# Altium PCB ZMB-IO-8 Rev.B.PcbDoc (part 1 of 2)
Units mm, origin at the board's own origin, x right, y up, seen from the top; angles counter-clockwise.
Board outline 164 x 122 mm, 8 copper layers (Top Layer, L2, L3, L4, L5, L6, L7, Bottom Layer), stack 1.966 mm thick; 31 components, 171 nets, 626 pads, 99 vias.
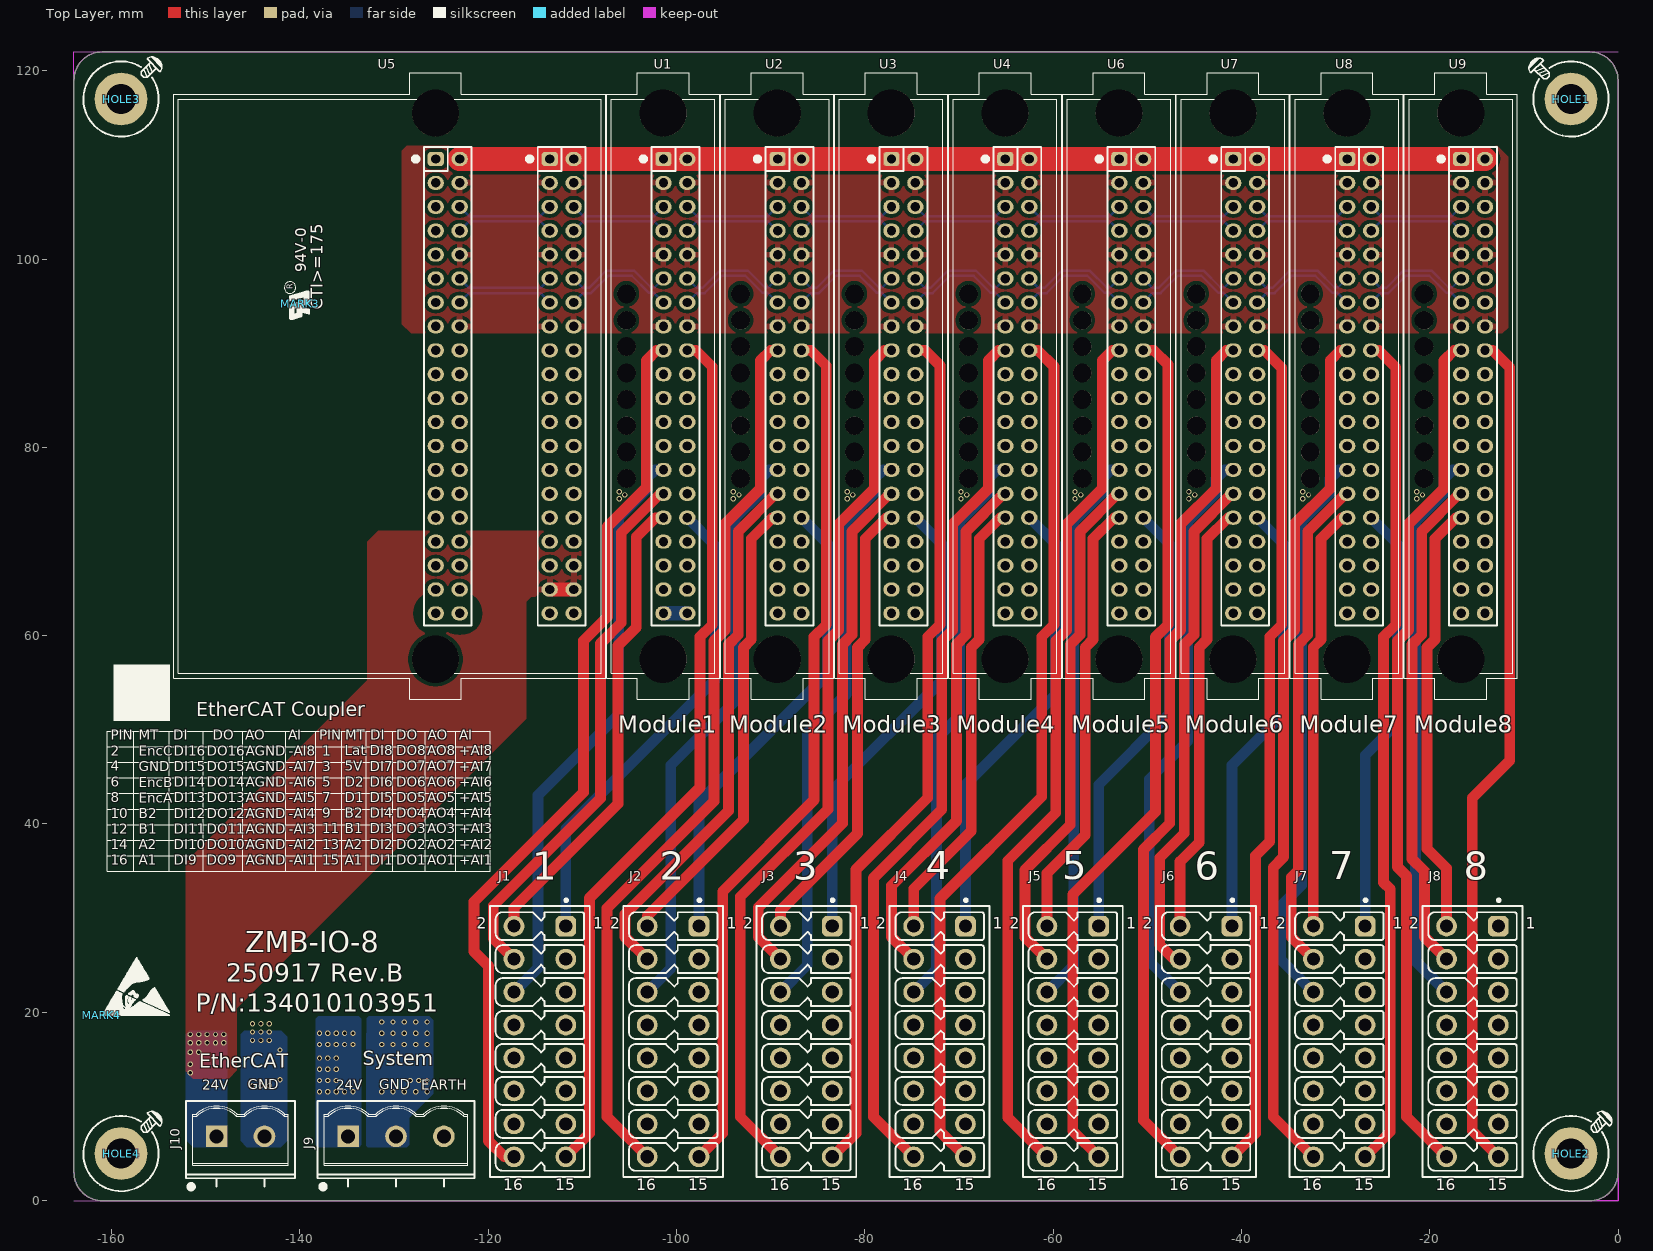
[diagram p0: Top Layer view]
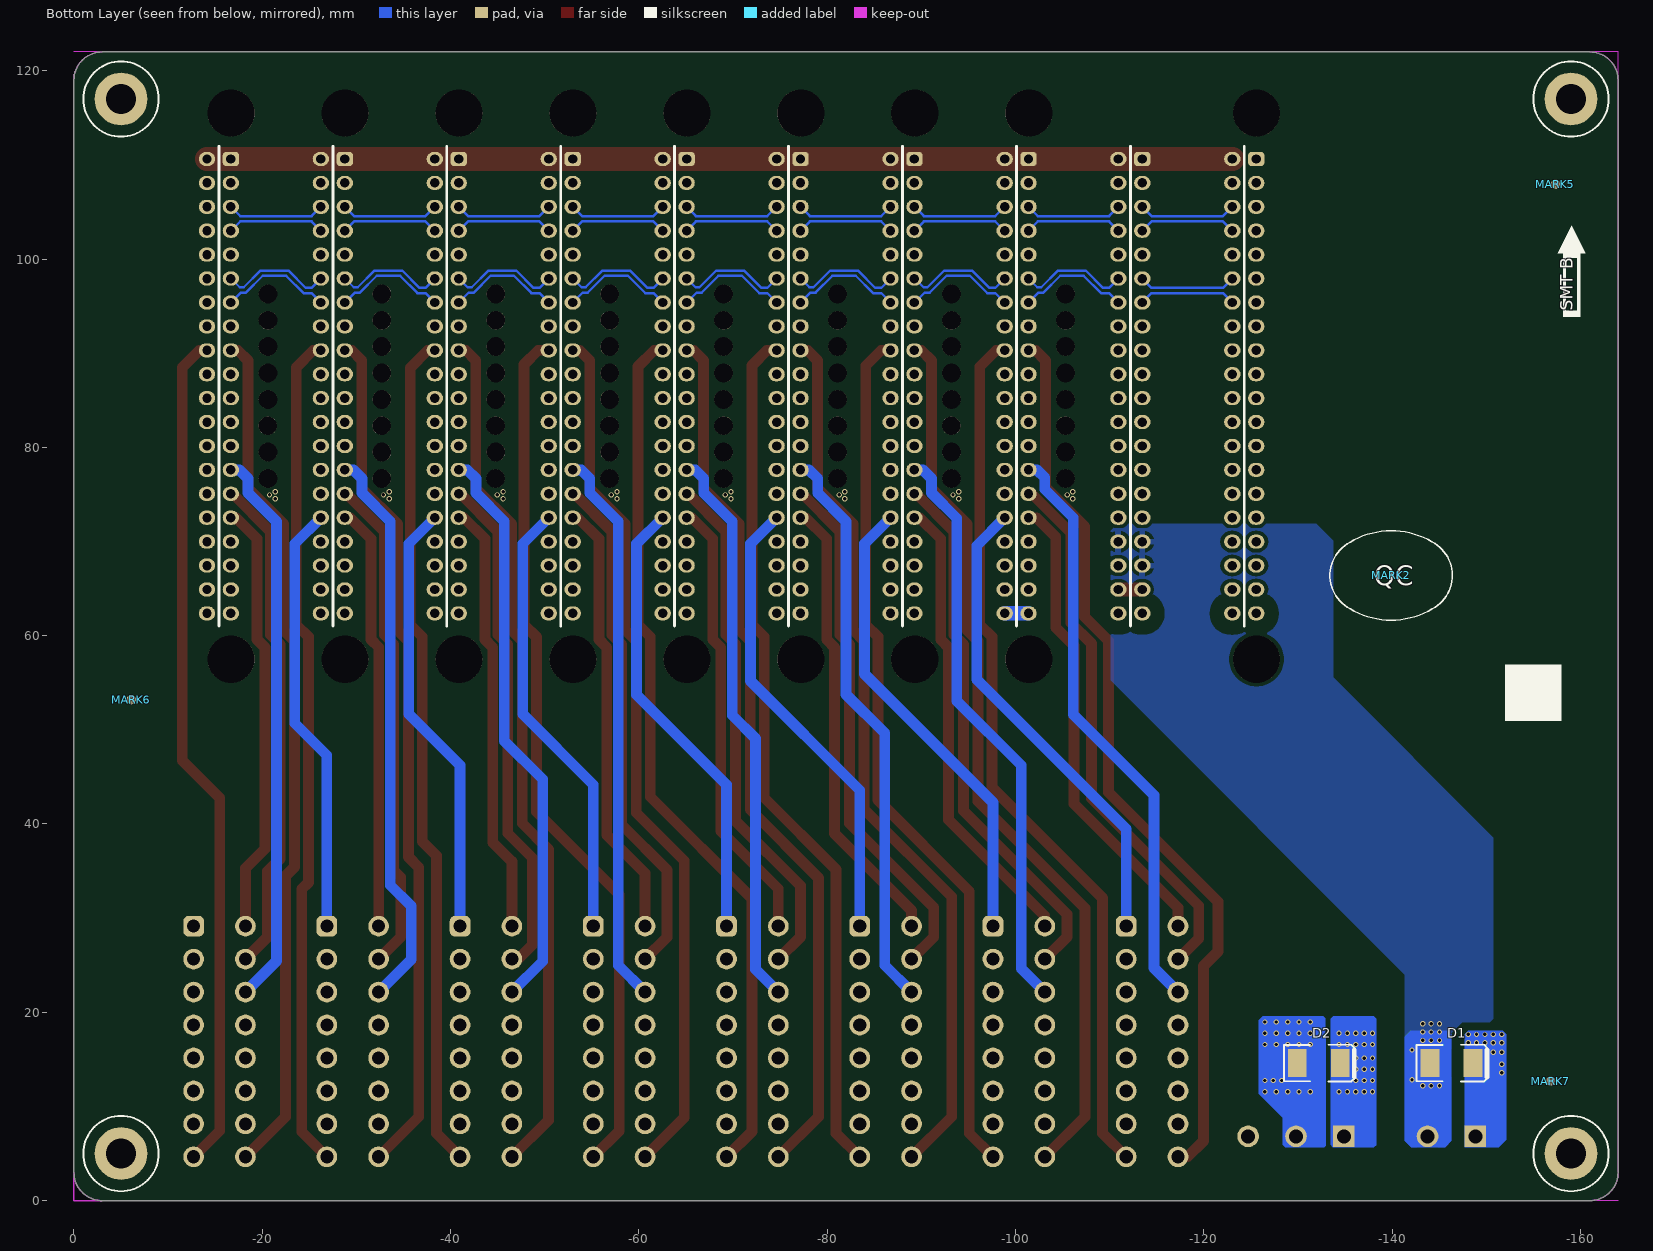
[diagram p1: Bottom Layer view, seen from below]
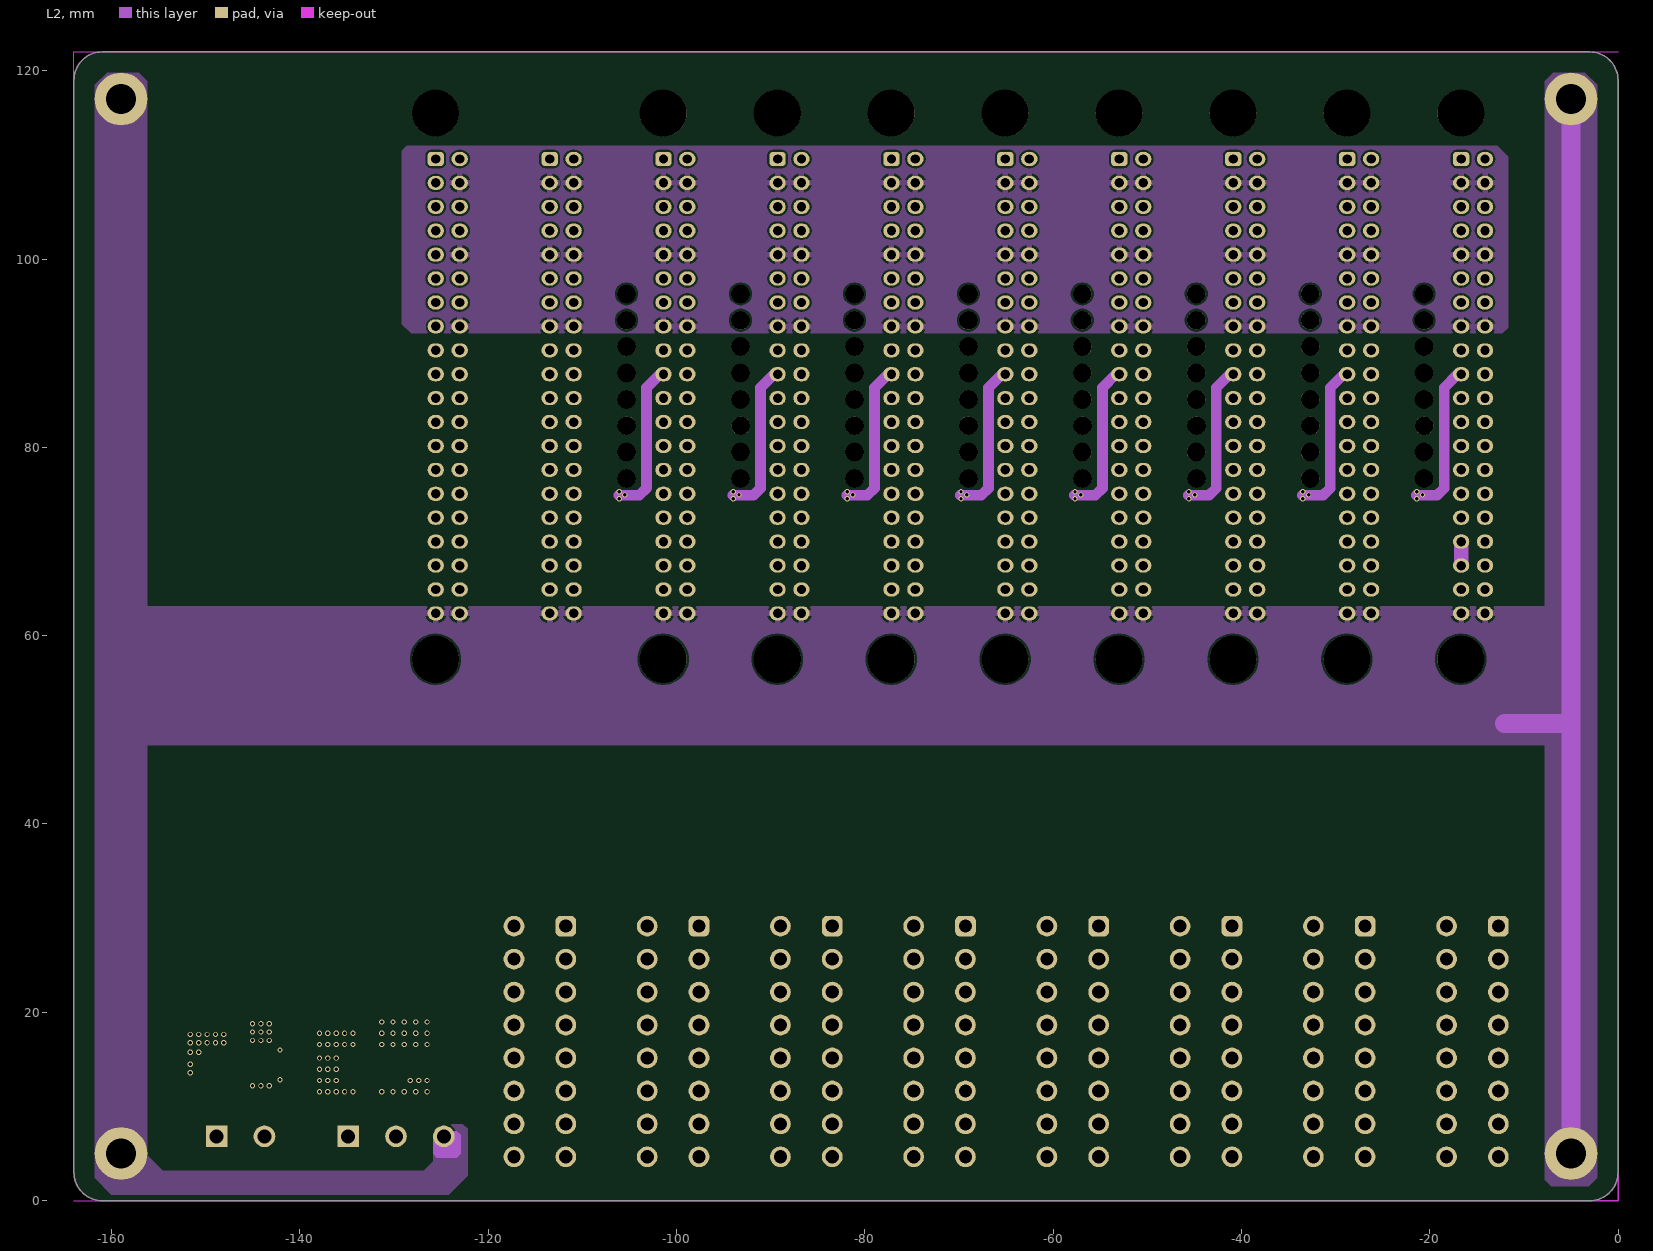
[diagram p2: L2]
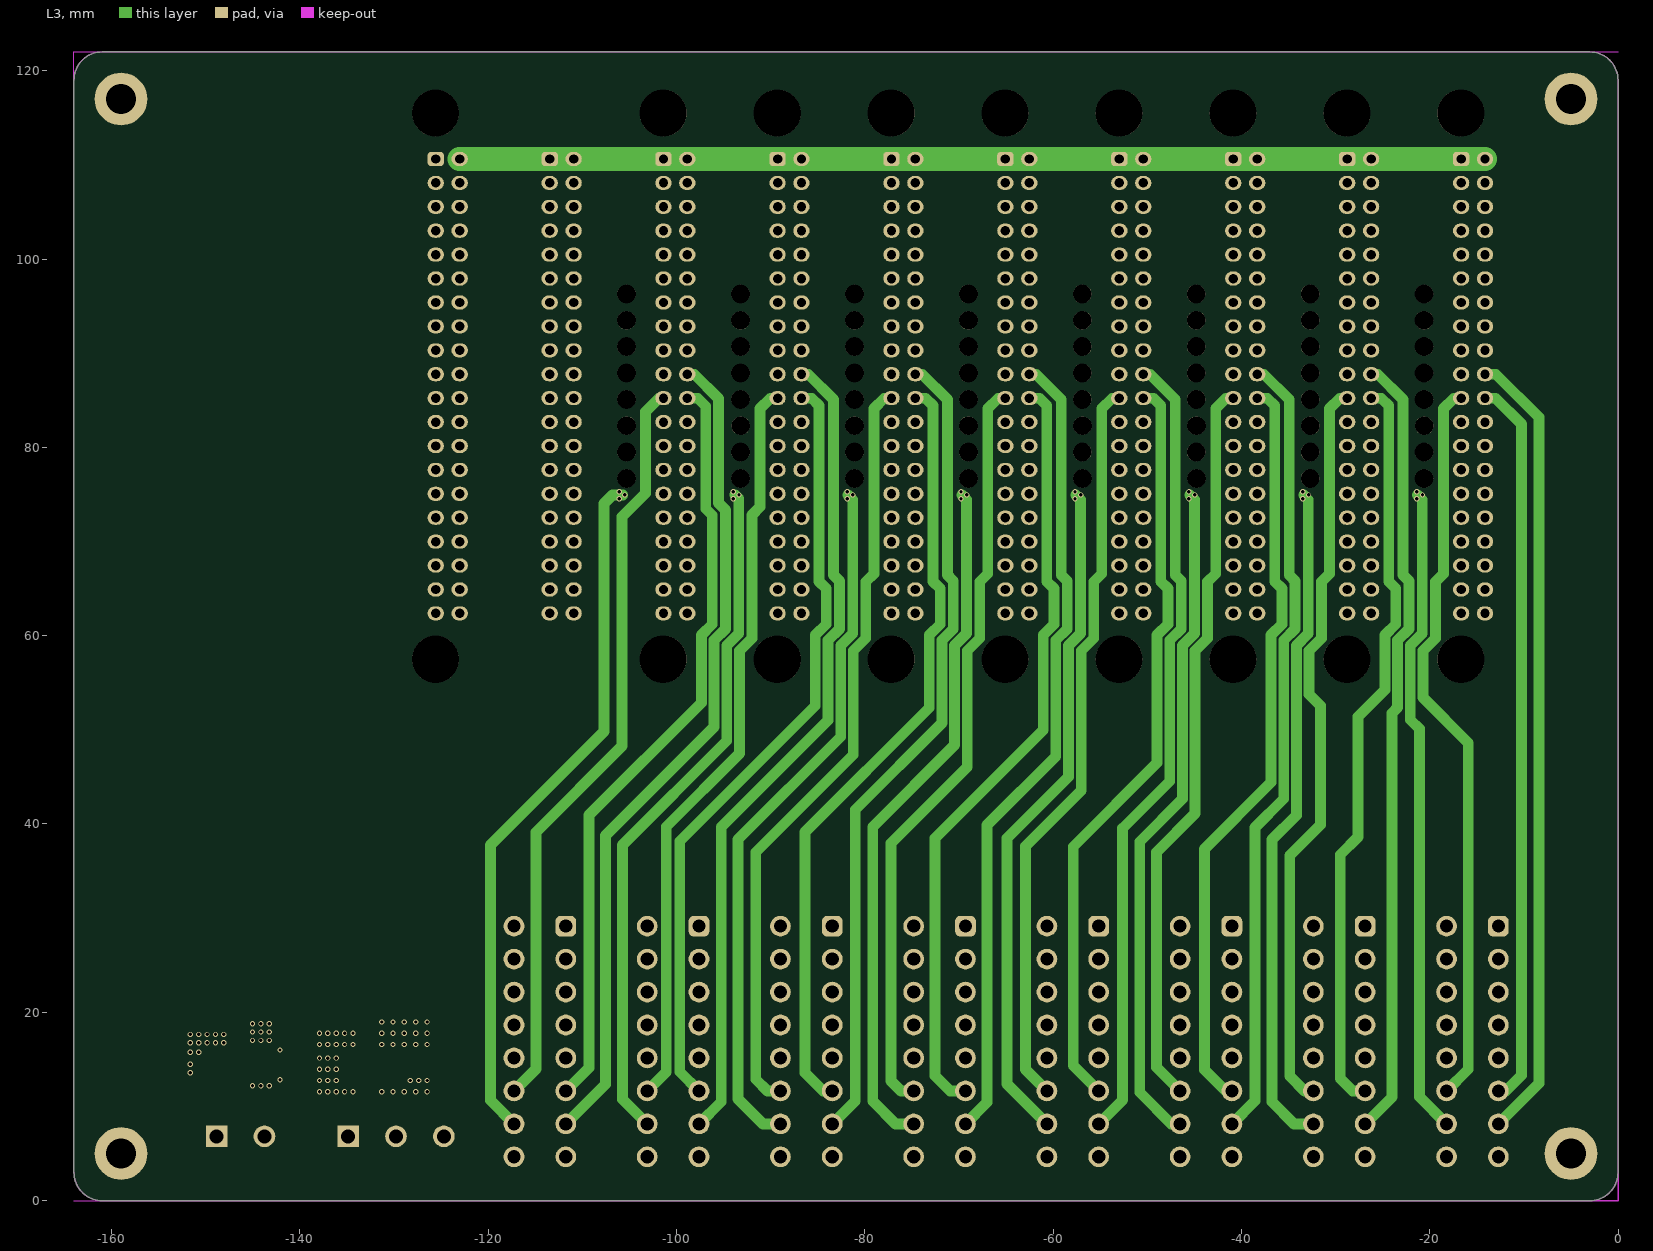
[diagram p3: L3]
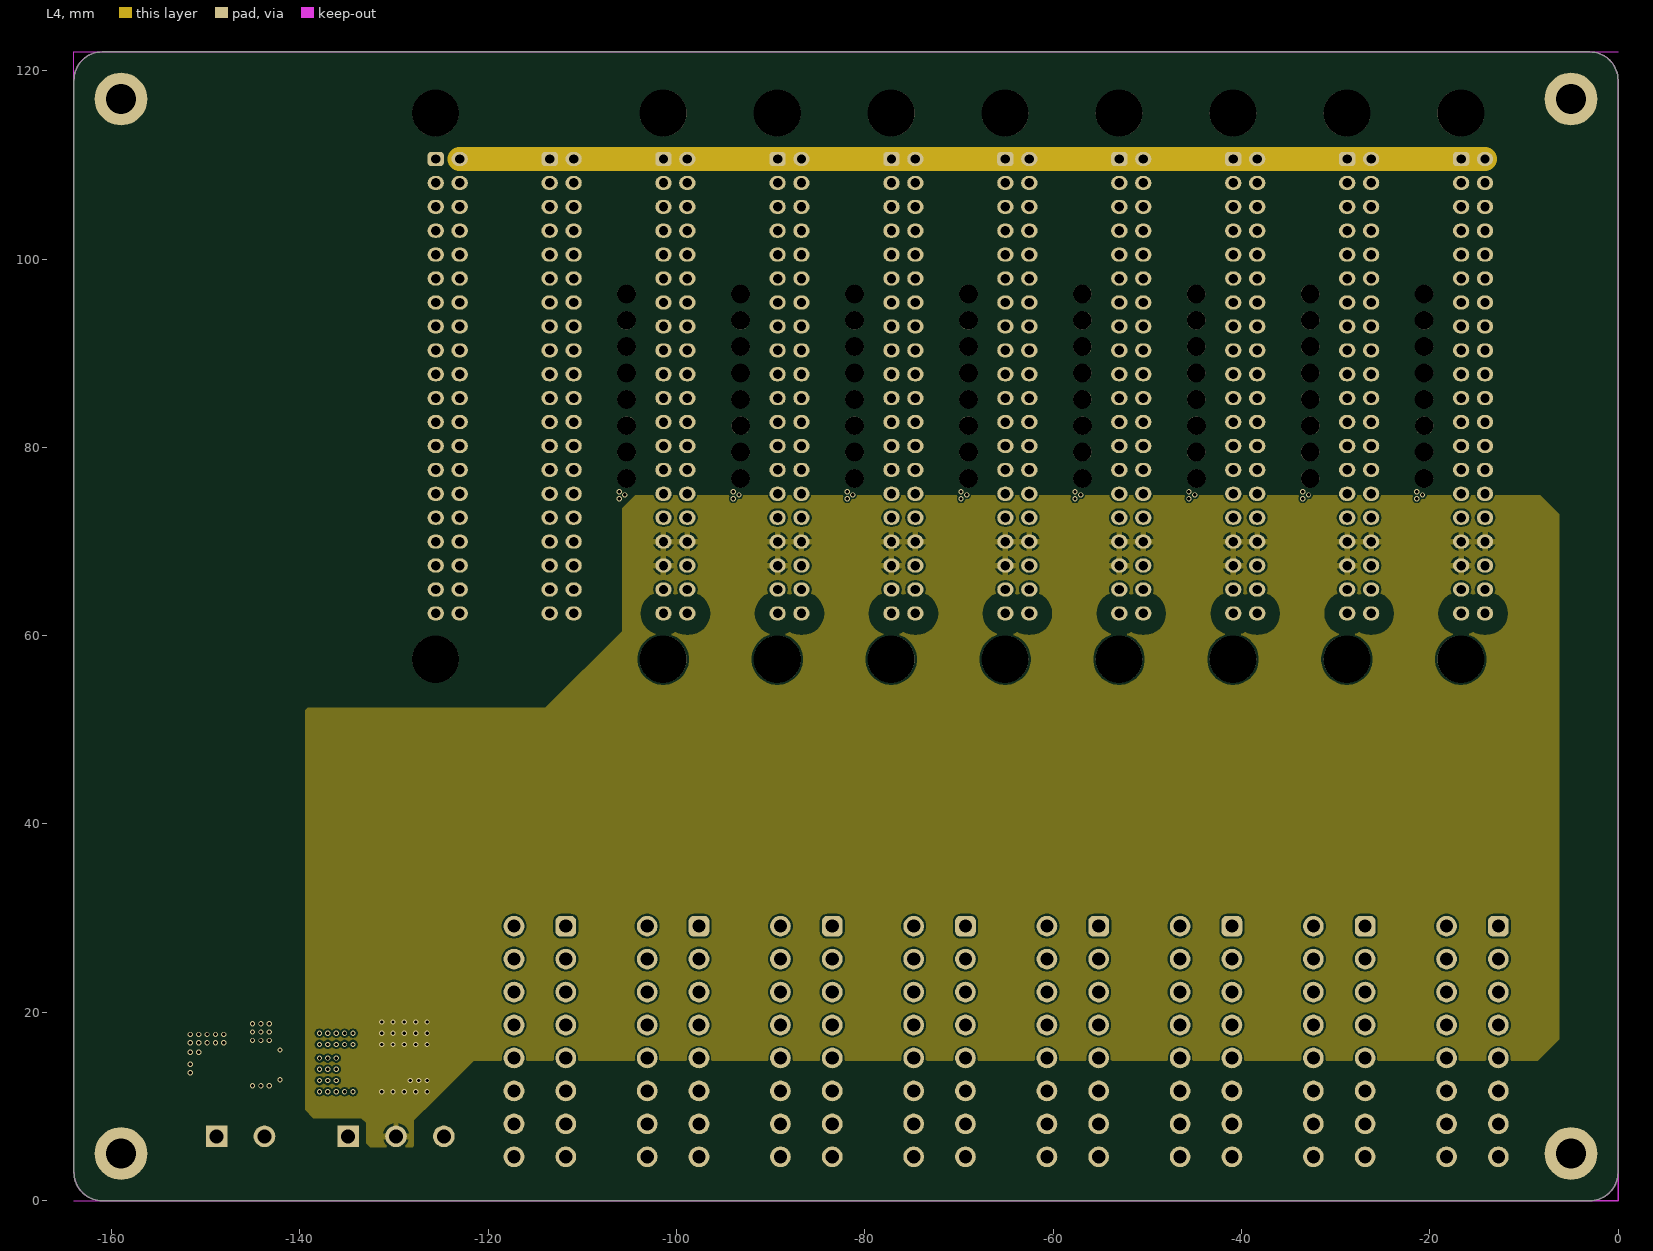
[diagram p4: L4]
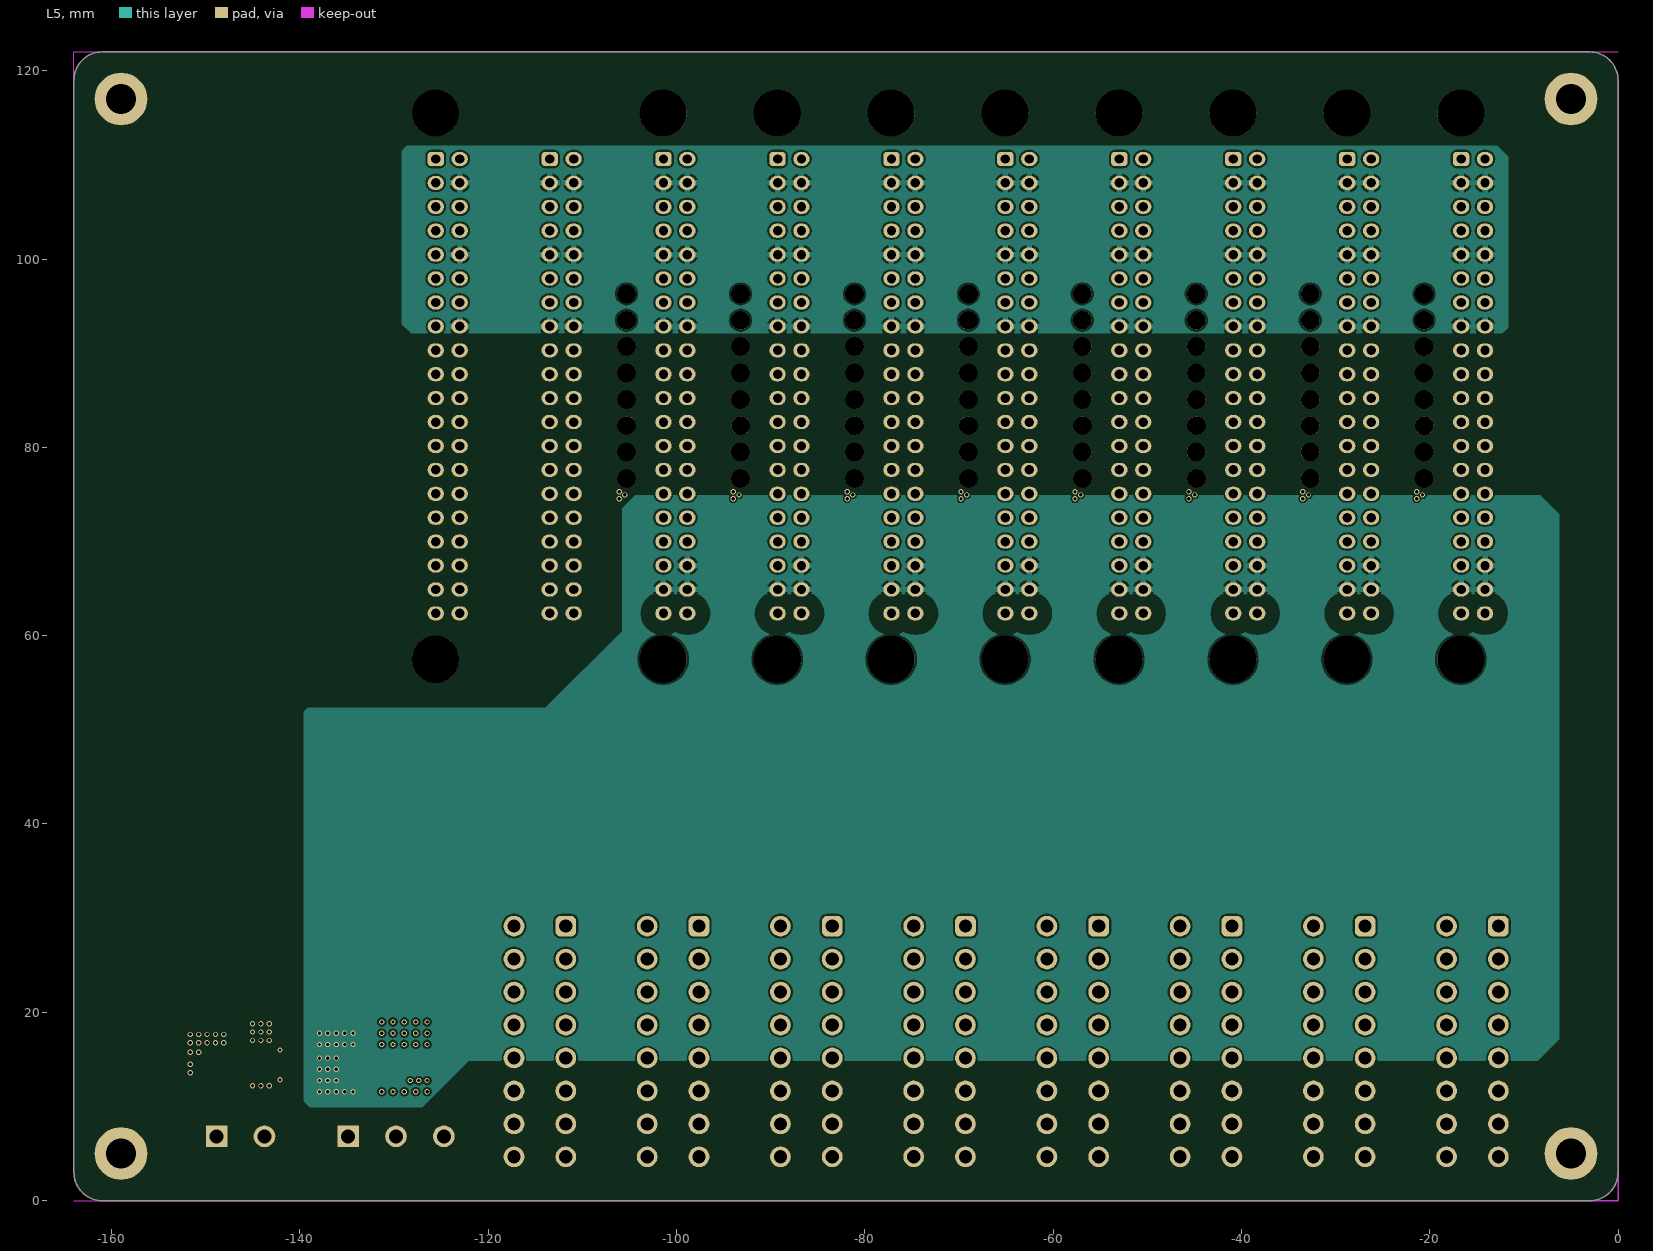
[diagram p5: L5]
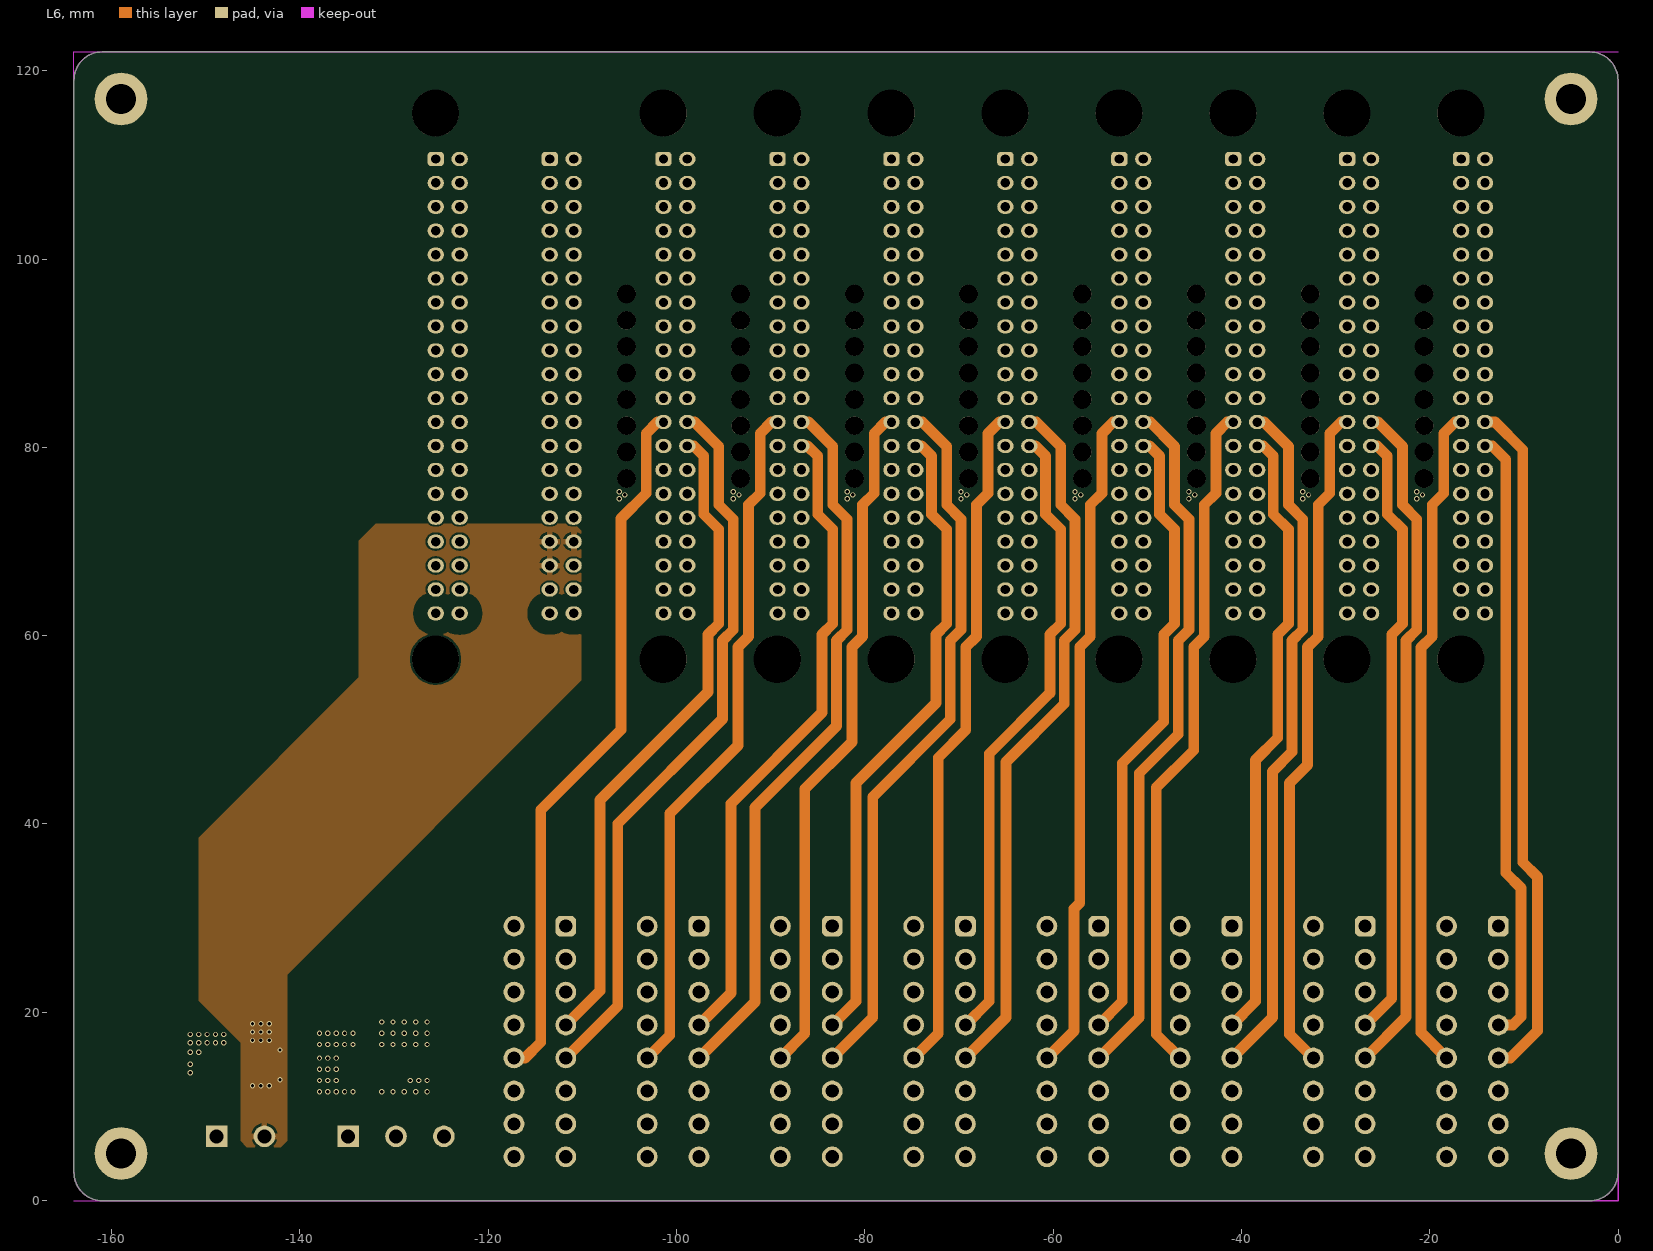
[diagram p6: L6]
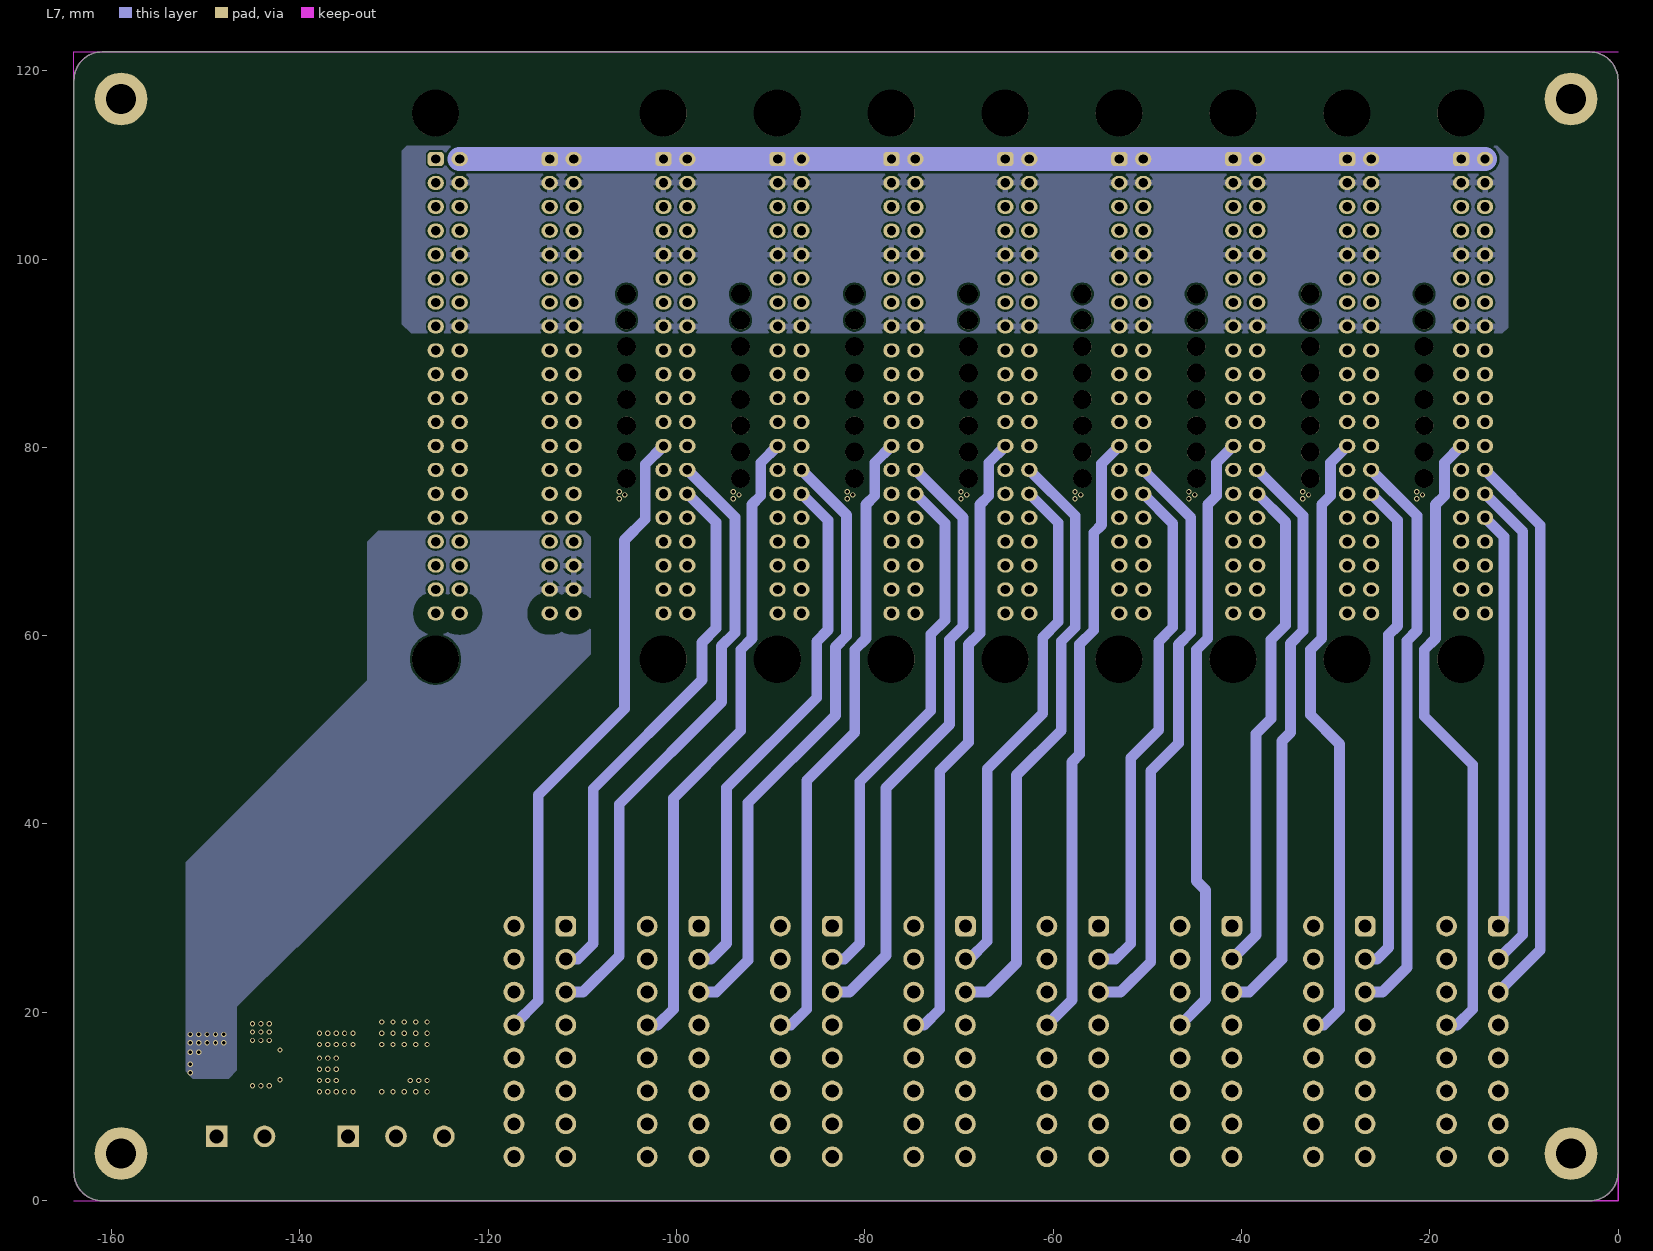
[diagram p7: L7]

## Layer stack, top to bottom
Top Solder: solder mask 0.0102, Solder Resist, Dk 3.2
Top Layer: signal copper 0.07
Dielectric 1: prepreg 0.081, FR-4, Dk 3.8
L2: signal copper 0.07
Dielectric 4: prepreg 0.0711, PP-006, Dk 4.1
L3: signal copper 0.035
Dielectric 6: prepreg 0.0711, PP-006, Dk 4.1
L4: signal copper 0.035
Dielectric 2: core 1.1, FR-4, Dk 4.2
L5: signal copper 0.035
Dielectric 7: prepreg 0.0711, PP-006, Dk 4.1
L6: signal copper 0.035
Dielectric 5: prepreg 0.0711, PP-006, Dk 4.1
L7: signal copper 0.07
Dielectric 3: prepreg 0.081, FR-4, Dk 3.8
Bottom Layer: signal copper 0.07
Bottom Solder: solder mask 0.0102, Solder Resist, Dk 3.2

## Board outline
-161,0 cw(c-161,3) -164,3 -164,119 cw(c-161,119) -161,122 -3,122 cw(c-3,119) 0,119 0,3 cw(c-3,3) -3,0

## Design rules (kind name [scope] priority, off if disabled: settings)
Clearance Clearance_diff2poly [InAnyDifferentialPair and IsTrack vs InPoly] p1: gap=0.508 ignorepadtopadclearanceinfootprint=FALSE except(0: Arc-Hole Track-Hole SMDPad-Hole THPad-Hole Via-Hole Fill-Hole Poly-Hole Region-Hole Text-Hole)
Clearance Clearance_moto2other [InNetClass('moto') vs InAnyNet > InNetClass('moto')] p2: gap=1.016 ignorepadtopadclearanceinfootprint=FALSE except(0: Arc-Hole Track-Hole SMDPad-Hole THPad-Hole Via-Hole Fill-Hole Poly-Hole Region-Hole Text-Hole)
Clearance Clearance_CAP90/270H->5 [((HasFootprint('0201C') or HasFootprint('0402C*') or HasFootprint('0603C*') or HasFootprint('0805C*') or HasFootprint('1210C') or HasFootprint('2220C')) and ((Rotation='0') or (Rotation='180'))) or (HasFootprint('1206C*')) and ((Rotation='90') or (Rotation='270')) vs (IsTrack > InAnyComponent) and OnLayer('Keep-Out Layer')  and (Y1=Y2)] p3: gap=5 ignorepadtopadclearanceinfootprint=FALSE except(0: Arc-Hole Track-Hole SMDPad-Hole THPad-Hole Via-Hole Fill-Hole Poly-Hole Region-Hole Text-Hole) // ZLG
Clearance Clearance_CAP0/180H->2 [((HasFootprint('0201C') or HasFootprint('0402C*') or HasFootprint('0603C*') or HasFootprint('0805C*') or HasFootprint('1210C') or HasFootprint('2220C')) and ((Rotation='90') or (Rotation='270'))) or (HasFootprint('1206C*')) and ((Rotation='0') or (Rotation='180')) vs (IsTrack > InAnyComponent) and OnLayer('Keep-Out Layer')  and (Y1=Y2)] p4: gap=2 ignorepadtopadclearanceinfootprint=FALSE except(0: Arc-Hole Track-Hole SMDPad-Hole THPad-Hole Via-Hole Fill-Hole Poly-Hole Region-Hole Text-Hole) // ZLG
Clearance Clearance_CAP90/270V>2 [((HasFootprint('0201C') or HasFootprint('0402C*') or HasFootprint('0603C*') or HasFootprint('0805C*') or HasFootprint('1210C') or HasFootprint('2220C')) and ((Rotation='0') or (Rotation='180'))) or (HasFootprint('1206C*')) and ((Rotation='90') or (Rotation='270')) vs (IsTrack > InAnyComponent) and OnLayer('Keep-Out Layer')  and (X1=X2)] p5: gap=2 ignorepadtopadclearanceinfootprint=FALSE except(0: Arc-Hole Track-Hole SMDPad-Hole THPad-Hole Via-Hole Fill-Hole Poly-Hole Region-Hole Text-Hole) // ZLG
Clearance Clearance_CAP0/180V>5 [((HasFootprint('0201C') or HasFootprint('0402C*') or HasFootprint('0603C*') or HasFootprint('0805C*') or HasFootprint('1210C') or HasFootprint('2220C')) and ((Rotation='90') or (Rotation='270'))) or (HasFootprint('1206C*')) and ((Rotation='0') or (Rotation='180')) vs (IsTrack > InAnyComponent) and OnLayer('Keep-Out Layer')  and (X1=X2)] p6: gap=5 ignorepadtopadclearanceinfootprint=FALSE except(0: Arc-Hole Track-Hole SMDPad-Hole THPad-Hole Via-Hole Fill-Hole Poly-Hole Region-Hole Text-Hole) // ZLG
Clearance Clearance_Keepout [OnLayer('Keep-Out Layer')] p7: gap=0.508 ignorepadtopadclearanceinfootprint=FALSE except(0: Arc-Hole Track-Hole SMDPad-Hole THPad-Hole Via-Hole Fill-Hole Poly-Hole Region-Hole Text-Hole) // ZLG
Clearance Clearance_Wave_Height<0.6mm [OnLayer('Bottom Layer') and IsSMTPin and (HasFootprint('0201*') or HasFootprint('0402*') or HasFootprint('0603R*')) > HasFootprint('0402C-H0.8') vs IsPadHoleValid > (IsFree or  HasFootprint('HOLE-*') or HasFootprint('SMDSTUD-*') or  HasFootprint('Mou-Hole-*') or HasFootprint('SMT*') or HasFootprint('HRS_*') or HasFootprint('MEDC52-32F-PCIE-*') or HasFootprint('PHONE-JACK*') or HasFootprint('SD-CARD-Panasonic')  or HasFootprint('SIM-ST-SIM-006P-NB2') or HasFootprint('MICROUSB-ST-USB-002B-1') or HasFootprint('USB_ST-USB-3316-2') )] p8: gap=3 ignorepadtopadclearanceinfootprint=FALSE except(0: Arc-Hole Track-Hole SMDPad-Hole THPad-Hole Via-Hole Fill-Hole Poly-Hole Region-Hole Text-Hole) // ZLG
Clearance Clearance_Wave_All [OnLayer('Bottom Layer') and IsSMTPin vs IsPadHoleValid > (IsFree or  HasFootprint('HOLE-*') or HasFootprint('SMDSTUD-*') or  HasFootprint('Mou-Hole-*') or HasFootprint('SMT*') or HasFootprint('HRS_*') or HasFootprint('MEDC52-32F-PCIE-*') or HasFootprint('PHONE-JACK*') or HasFootprint('SD-CARD-Panasonic')  or HasFootprint('SIM-ST-SIM-006P-NB2') or HasFootprint('MICROUSB-ST-USB-002B-1') or HasFootprint('USB_ST-USB-3316-2') )] p9: gap=4 ignorepadtopadclearanceinfootprint=FALSE except(0: Arc-Hole Track-Hole SMDPad-Hole THPad-Hole Via-Hole Fill-Hole Poly-Hole Region-Hole Text-Hole) // ZLG
Clearance Clearance_earth2other [InNet('EARTH*') or InNet('PGND*') vs InPoly] p10: gap=1.524 ignorepadtopadclearanceinfootprint=FALSE except(0: Arc-Hole Track-Hole SMDPad-Hole THPad-Hole Via-Hole Fill-Hole Poly-Hole Region-Hole Text-Hole) // ZLG
Clearance Clearance_TP [HasFootprint('PAD-40') vs HasFootprint('PAD-40')] p11: gap=1.27 ignorepadtopadclearanceinfootprint=FALSE except(0: Arc-Hole Track-Hole SMDPad-Hole THPad-Hole Via-Hole Fill-Hole Poly-Hole Region-Hole Text-Hole) // ZLG
Clearance Clearance_Hole2Pad [IsVia vs IsPad  > ( HasFootprint('QF*-*N*') or HasFootprint('SO*-*N*') or HasFootprint('PQFN*') or HasFootprint('PSON*') or HasFootprint('DFN*') or HasFootprint('DPAK*') or HasFootprint('PVQF*') )] p12: gap=0 ignorepadtopadclearanceinfootprint=FALSE // ZLG
Clearance Clearance_Surface [OnLayer('Top Layer') or OnLayer('Bottom Layer')] p13: gap=0.203 ignorepadtopadclearanceinfootprint=FALSE except(0: Arc-Hole Track-Hole SMDPad-Hole THPad-Hole Via-Hole Fill-Hole Poly-Hole Region-Hole Text-Hole; 0.254: Via-Poly; 0.305: Poly-Region Poly-Text; 0.381: Arc-Poly Track-Poly SMDPad-Poly THPad-Poly Fill-Poly Poly-Poly) // ZLG
Clearance [All] p14: gap=0.203 ignorepadtopadclearanceinfootprint=FALSE except(0: Arc-Hole Track-Hole SMDPad-Hole THPad-Hole Via-Hole Fill-Hole Poly-Hole Region-Hole Text-Hole; 0.305: Arc-Poly Track-Poly SMDPad-Poly Fill-Poly Poly-Poly Poly-Text) // ZLG
DiffPairsRouting [All] p1: maxlimit=0.305 minlimit=0.305 mostfreqgap=0.305 toplayer_minwidth=0.254 toplayer_maxwidth=0.254 toplayer_prefwidth=0.254 midlayer1_minwidth=0.254 midlayer1_maxwidth=0.254 midlayer1_prefwidth=0.254 midlayer2_minwidth=0.254 midlayer2_maxwidth=0.254 midlayer2_prefwidth=0.254 midlayer3_minwidth=0.254 midlayer3_maxwidth=0.254 midlayer3_prefwidth=0.254 midlayer4_minwidth=0.254 midlayer4_maxwidth=0.254 midlayer4_prefwidth=0.254 midlayer5_minwidth=0.254 midlayer5_maxwidth=0.254 midlayer5_prefwidth=0.254 midlayer6_minwidth=0.254 midlayer6_maxwidth=0.254 midlayer6_prefwidth=0.254 bottomlayer_minwidth=0.254 bottomlayer_maxwidth=0.254 bottomlayer_prefwidth=0.254 maxuncoupledlength=12.7
HoleSize [All] p1: absolutevalues=TRUE maxlimit=25.4 minlimit=0.025 maxpercent=80.000 minpercent=20.000
MatchedLengths MatchedLengths-InAnyDifferentialPair [InAnyDifferentialPair] p1: tolerance=0.127 checknetsindiffpair=TRUE checkdiffpairvsdiffpair=FALSE checkxsignals=FALSE checkothers=FALSE
MinimumSolderMaskSliver [All] p1: minsoldermaskwidth=0.102
PlaneClearance PlaneClearance_Ermet [HasFootprint('ermet*')] p1: clearance=0.254 // ZLG
PlaneClearance PlaneClearance_BGA(min7mil) [isvia and WithinRoom('BGA')] p2: clearance=0.203 // ZLG
PlaneClearance PlaneClearance_Full [IsVia] p3: clearance=0.254 // ZLG
PlaneClearance [All] p4: clearance=0.508 // ZLG
PlaneConnect PlaneConnect_Full [IsVia or HasFootprint('PAD-35/50') or  HasFootprint('HOLE-*')] p1: planeconnectstyle=Direct reliefexpansion=0.508 reliefentries=4 reliefconductorwidth=0.254 reliefairgap=0.254 // ZLG
PlaneConnect [All] p2: planeconnectstyle=Relief reliefexpansion=0.406 reliefentries=4 reliefconductorwidth=0.381 reliefairgap=0.152 // ZLG
PolygonConnect PolygonConnect_SMDHole [HasFootprint('Mou-Hole-*') or HasFootprint('SMDSTUD-*')] p1: connectstyle=Relief reliefconductorwidth=2.032 reliefentries=4 polygonreliefangle="45 Angle" airgapwidth=0.508 // ZLG
PolygonConnect PolygonConnect_Full [IsVia or   HasFootprint('PAD-40') or   HasFootprint('PAD-35/50') or  HasFootprint('HOLE-*') or HasFootprint('RESC4532X32*') or HasFootprint('1206*')] p2: connectstyle=Direct reliefconductorwidth=0.254 reliefentries=4 polygonreliefangle="90 Angle" airgapwidth=0.254 // ZLG
PolygonConnect PolygonConnect_Surface [OnLayer('Top Layer')  or  OnLayer('Bottom Layer')] p3: connectstyle=Relief reliefconductorwidth=0.635 reliefentries=4 polygonreliefangle="90 Angle" airgapwidth=0.381 // ZLG
PolygonConnect PolygonConnect_Inner [All] p4: connectstyle=Relief reliefconductorwidth=0.635 reliefentries=4 polygonreliefangle="90 Angle" airgapwidth=0.254 // ZLG
RoutingVias [All] p1: holewidth=0.356 width=0.559 viastyle="Through Hole" minholewidth=0.356 minwidth=0.559 maxholewidth=0.356 maxwidth=0.559 // ZLG
SilkToSilkClearance [istext > StringText like'SMT*' vs All > HasFootprint('ZY_no Pb-*')] p1: silktosilkclearance=0.025 // ZLG
SilkToSolderMaskClearance SilkToSolderMaskClearance_WAV [(HasFootprint('SOP*') or HasFootprint('SOIC*') or HasFootprint('SOD*') or HasFootprint('DO-214*') or HasFootprint('BGA*') or HasFootprint('FFCS*') or HasFootprint('FFCF*') or HasFootprint('SMTCON_*') or HasFootprint('HRS_*') ) and IsComponentTrack and  OnBottomSilkscreen vs IsPadHoleValid > (IsFree or  HasFootprint('HOLE-*') or HasFootprint('SMDSTUD-*') or  HasFootprint('Mou-Hole-*') or HasFootprint('SMT*') or HasFootprint('HRS_*') or HasFootprint('MEDC52-32F-PCIE-*') or HasFootprint('PHONE-JACK*') or HasFootprint('SD-CARD-Panasonic')  or HasFootprint('SIM-ST-SIM-006P-NB2') or HasFootprint('MICROUSB-ST-USB-002B-1') or HasFootprint('USB_ST-USB-3316-2') )] p1: minsilkscreentomaskgap=4 clearancetoexposedcopper=TRUE // ZLG
SilkToSolderMaskClearance [IsPad vs IsText] p2: minsilkscreentomaskgap=0.025 clearancetoexposedcopper=TRUE // ZLG
SolderMaskExpansion [All] p1: expansion=0.102 istentingtop=FALSE
Width [All] p1: maxlimit=5.08 minlimit=0.203 preferedwidth=0.203 // ZLG
23 further rules are at their usual default settings.

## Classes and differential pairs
differential pair NewDifferentialPair1: +NetU5_A12 -NetU5_A14
differential pair RX1G: +"" -""
differential pair RX0A: +"" -""
differential pair TX1H: +"" -""
differential pair RX1A: +"" -""
differential pair RX1D: +"" -""
differential pair RX0E: +"" -""
differential pair RX0D: +"" -""
differential pair RX: +"" -""
differential pair RX1C: +"" -""
differential pair RX1F: +"" -""
differential pair RX0G: +"" -""
differential pair RX1H: +"" -""
differential pair RX1B: +"" -""
differential pair RX0F: +"" -""
differential pair RX0C: +"" -""
differential pair RX1E: +"" -""
differential pair RX0B: +"" -""
differential pair RX0H: +"" -""
differential pair DP1: +"" -""
differential pair DP2: +"" -""
differential pair DP3: +"" -""
differential pair DP4: +"" -""
differential pair DP5: +"" -""
differential pair DP6: +"" -""
differential pair DP7: +"" -""
differential pair DP8: +"" -""
differential pair DP9: +"" -""
differential pair DP10: +"" -""
differential pair DP11: +"" -""
differential pair DP12: +"" -""
differential pair DP13: +"" -""
differential pair DP14: +"" -""
differential pair DP15: +"" -""
differential pair DP16: +"" -""
differential pair DP17: +"" -""
differential pair DP18: +"" -""

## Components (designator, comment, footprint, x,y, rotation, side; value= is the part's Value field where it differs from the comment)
D1 "SMBJ30A,DO-214AA" SOD-1812D -146.304,14.605 r180 bottom
D2 "SMBJ30A,DO-214AA" SOD-1812D -132.207,14.605 r180 bottom
HOLE1 "HOLE - 螺丝孔" "HOLE-3.2 - Screw" -5,117 r90 top locked
HOLE2 "HOLE - 螺丝孔" "HOLE-3.2 - Screw" -5,5 r0 top locked
HOLE3 "HOLE - 螺丝孔" "HOLE-3.2 - Screw" -159,117 r0 top locked
HOLE4 "HOLE - 螺丝孔" "HOLE-3.2 - Screw" -159,5 r0 top locked
J1 "15EDGVHC" DEGSON_15EDGVHC-THR-3.5-16P-1Y-1000Z(H)-PA -114.511,16.9 r270 top locked
J2 "15EDGVHC" DEGSON_15EDGVHC-THR-3.5-16P-1Y-1000Z(H)-PA -100.362,16.9 r270 top locked
J3 "15EDGVHC" DEGSON_15EDGVHC-THR-3.5-16P-1Y-1000Z(H)-PA -86.212,16.9 r270 top locked
J4 "15EDGVHC" DEGSON_15EDGVHC-THR-3.5-16P-1Y-1000Z(H)-PA -72.062,16.9 r270 top locked
J5 "15EDGVHC" DEGSON_15EDGVHC-THR-3.5-16P-1Y-1000Z(H)-PA -57.912,16.9 r270 top locked
J6 "15EDGVHC" DEGSON_15EDGVHC-THR-3.5-16P-1Y-1000Z(H)-PA -43.762,16.9 r270 top locked
J7 "15EDGVHC" DEGSON_15EDGVHC-THR-3.5-16P-1Y-1000Z(H)-PA -29.612,16.9 r270 top locked
J8 "15EDGVHC" DEGSON_15EDGVHC-THR-3.5-16P-1Y-1000Z(H)-PA -15.462,16.9 r270 top locked
J9 "2EDGVC-5.08-03P-14-00AH,180°" CON508P1664L820W140D35S-3DIP -129.794,6.477 r0 top
J10 "2EDGVC-5.08-02P-14-00AH,180°" CON508P1156L820W140D35S-2DIP -146.304,6.477 r0 top
MARK2 "ZY QC" ZY_QC -139.9,66.4 r180 bottom
MARK3 "UR" ZY_UR-3X2 -139.954,95.25 r90 top
MARK4 "ZY_ESD-MARK" ZY_ESD-7 -161.036,19.685 r0 top
MARK5 "MARKER" MARKER-C-1.0M -157.353,107.95 r180 bottom
MARK6 "MARKER" MARKER-C-1.0M -6.096,53.213 r180 bottom
MARK7 "MARKER" MARKER-C-1.0M -156.845,12.7 r180 bottom
U1 "=Value" ZIOC-E1600DX -102.082,86.5 r0 top locked
U2 "=Value" ZIOC-E1600DX -89.965,86.5 r0 top locked
U3 "=Value" ZIOC-E0016DX -77.865,86.5 r0 top locked
U4 "=Value" ZIOC-E0016DX -65.765,86.5 r0 top locked
U5 "=Value" ZCPC-80801 -118.265,86.5 r0 top locked
U6 "=Value" ZIOC-E0008AX -53.665,86.5 r0 top locked
U7 "=Value" ZIOC-E0008AX -41.565,86.5 r0 top locked
U8 "=Value" ZIOC-E0800AX -29.465,86.5 r0 top locked
U9 "=Value" ZIOC-E0800AX -17.365,86.5 r0 top locked

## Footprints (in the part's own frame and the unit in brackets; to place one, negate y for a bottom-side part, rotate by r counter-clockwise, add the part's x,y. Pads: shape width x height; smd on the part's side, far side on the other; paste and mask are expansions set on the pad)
CON508P1156L820W140D35S-2DIP [mm] "ZLGLIB"
  rect 2.3x2.3 hole 1.5: 1(-2.54,0.35)
  round 2.3 hole 1.5: 2(2.54,0.35)
  silkscreen extent -5.78,-5.25 5.78,4.1, body extent -5.97,-4.32 6.03,4.28, height 12.01
CON508P1664L820W140D35S-3DIP [mm] "ZLGLIB"
  rect 2.3x2.3 hole 1.5: 1(-5.08,0.35)
  round 2.3 hole 1.5: 2(0,0.35) 3(5.08,0.35)
  silkscreen extent -8.32,-5.25 8.32,4.1, body extent -8.5,-4.32 8.5,4.28, height 12.01
DEGSON_15EDGVHC-THR-3.5-16P-1Y-1000Z(H)-PA [mm] "ZLGLIB"
  rrect50% 2.2x2.2 hole 1.4: 1(-12.25,2.75)
  round 2.2 hole 1.4: 2(-12.25,-2.75) 3(-8.75,2.75) 4(-8.75,-2.75) 5(-5.25,2.75) 6(-5.25,-2.75) 7(-1.75,2.75) 8(-1.75,-2.75) 9(1.75,2.75) 10(1.75,-2.75) 11(5.25,2.75) 12(5.25,-2.75) 13(8.75,2.75) 14(8.75,-2.75) 15(12.25,2.75) 16(12.25,-2.75)
  silkscreen extent -15.15,-5.3 14.4,5.3, body extent -14.4,-5.46 14.4,5.14, height 10.03
"HOLE-3.2 - Screw" [mm]
  round 5.6 hole 3.2: 1(0,0)
  silkscreen extent -4,-4 4.34,4.48
MARKER-C-1.0M [mm]
  round 1 smd paste-1.016 mask+0.5: 0(0,0)
  Top Layer pour cut-out: -1.1,0 -1.016,-0.421 -0.778,-0.778 -0.421,-1.016 0,-1.1 0,-1.1 0.421,-1.016 0.778,-0.778 1.016,-0.421 1.1,0 1.1,0 1.016,0.421 0.778,0.778 0.421,1.016 0,1.1 0,1.1 -0.421,1.016 -0.778,0.778 -1.016,0.421 -1.1,0
SOD-1812D [mm] "ZLGLIB"
  rect 2x3 smd: 1(-2.286,0) 2(2.286,0)
  Top Layer pour cut-out: -1.27,1.499 -1.27,-1.499 1.245,-1.499 1.245,1.499
  silkscreen extent -3.71,-1.95 3.86,1.95, body extent -2.77,-1.96 2.83,1.94, height 2.5
ZCPC-80801 [mm]
  rrect50% 1.74x1.5 hole 1: A1(-7.305,24.13) B1(4.795,24.13)
  oval 1.74x1.5 hole 1: A2(-4.765,24.13) A3(-7.305,21.59) A4(-4.765,21.59) A5(-7.305,19.05) A6(-4.765,19.05) A7(-7.305,16.51) A8(-4.765,16.51) A9(-7.305,13.97) A10(-4.765,13.97) A11(-7.305,11.43) A12(-4.765,11.43) A13(-7.305,8.89) A14(-4.765,8.89) A15(-7.305,6.35) A16(-4.765,6.35) A17(-7.305,3.81) A18(-4.765,3.81) A19(-7.305,1.27) A20(-4.765,1.27) A21(-7.305,-1.27) A22(-4.765,-1.27) A23(-7.305,-3.81) A24(-4.765,-3.81) A25(-7.305,-6.35) A26(-4.765,-6.35) A27(-7.305,-8.89) A28(-4.765,-8.89) A29(-7.305,-11.43) A30(-4.765,-11.43) A31(-7.305,-13.97) A32(-4.765,-13.97) A33(-7.305,-16.51) A34(-4.765,-16.51) A35(-7.305,-19.05) A36(-4.765,-19.05) A37(-7.305,-21.59) A38(-4.765,-21.59) A39(-7.305,-24.13) A40(-4.765,-24.13) B2(7.335,24.13) B3(4.795,21.59) B4(7.335,21.59) B5(4.795,19.05) B6(7.335,19.05) B7(4.795,16.51) B8(7.335,16.51) B9(4.795,13.97) B10(7.335,13.97) B11(4.795,11.43) B12(7.335,11.43) B13(4.795,8.89) B14(7.335,8.89) B15(4.795,6.35) B16(7.335,6.35) B17(4.795,3.81) B18(7.335,3.81) B19(4.795,1.27) B20(7.335,1.27) B21(4.795,-1.27) B22(7.335,-1.27) B23(4.795,-3.81) B24(7.335,-3.81) B25(4.795,-6.35) B26(7.335,-6.35) B27(4.795,-8.89) B28(7.335,-8.89) B29(4.795,-11.43) B30(7.335,-11.43) B31(4.795,-13.97) B32(7.335,-13.97) B33(4.795,-16.51) B34(7.335,-16.51) B35(4.795,-19.05) B36(7.335,-19.05) B37(4.795,-21.59) B38(7.335,-21.59) B39(4.795,-24.13) B40(7.335,-24.13)
  round 4.95 hole 5 unplated: ""(-7.335,-29) ""(-7.335,29)
  Top Layer lines w1.27: 7.335,6.35 7.335,6.35
  silkscreen extent -35.15,-33.27 10.77,33.27, body extent -8.53,-25.8 8.57,25.4, height 8.51
ZIOC-E0008AX [mm]
  rrect50% 1.74x1.5 hole 1: 1(0.695,24.13)
  oval 1.74x1.5 hole 1: 2(3.235,24.13) 3(0.695,21.59) 4(3.235,21.59) 5(0.695,19.05) 6(3.235,19.05) 7(0.695,16.51) 8(3.235,16.51) 9(0.695,13.97) 10(3.235,13.97) 11(0.695,11.43) 12(3.235,11.43) 13(0.695,8.89) 14(3.235,8.89) 15(0.695,6.35) 16(3.235,6.35) 17(0.695,3.81) 18(3.235,3.81) 19(0.695,1.27) 20(3.235,1.27) 21(0.695,-1.27) 22(3.235,-1.27) 23(0.695,-3.81) 24(3.235,-3.81) 25(0.695,-6.35) 26(3.235,-6.35) 27(0.695,-8.89) 28(3.235,-8.89) 29(0.695,-11.43) 30(3.235,-11.43) 31(0.695,-13.97) 32(3.235,-13.97) 33(0.695,-16.51) 34(3.235,-16.51) 35(0.695,-19.05) 36(3.235,-19.05) 37(0.695,-21.59) 38(3.235,-21.59) 39(0.695,-24.13) 40(3.235,-24.13)
  round 1.95 hole 2 unplated: ""(-3.235,7) ""(-3.235,9.8) ""(-3.235,-7) ""(-3.235,-1.4) ""(-3.235,1.4) ""(-3.235,4.2) ""(-3.218,-9.8) ""(-3.218,-4.2)
  round 4.95 hole 5 unplated: ""(0.665,-29) ""(0.665,29)
  Top Layer lines w0.508: 0.154,-13.97 0.695,-13.97 ; 0.695,-11.688 0.695,-11.43
  silkscreen extent -5.33,-33.27 6.67,33.27, body extent -0.53,-25.8 4.47,25.4, height 8.51
ZIOC-E0016DX [mm]
  rrect50% 1.74x1.5 hole 1: 1(0.695,24.13)
  oval 1.74x1.5 hole 1: 2(3.235,24.13) 3(0.695,21.59) 4(3.235,21.59) 5(0.695,19.05) 6(3.235,19.05) 7(0.695,16.51) 8(3.235,16.51) 9(0.695,13.97) 10(3.235,13.97) 11(0.695,11.43) 12(3.235,11.43) 13(0.695,8.89) 14(3.235,8.89) 15(0.695,6.35) 16(3.235,6.35) 17(0.695,3.81) 18(3.235,3.81) 19(0.695,1.27) 20(3.235,1.27) 21(0.695,-1.27) 22(3.235,-1.27) 23(0.695,-3.81) 24(3.235,-3.81) 25(0.695,-6.35) 26(3.235,-6.35) 27(0.695,-8.89) 28(3.235,-8.89) 29(0.695,-11.43) 30(3.235,-11.43) 31(0.695,-13.97) 32(3.235,-13.97) 33(0.695,-16.51) 34(3.235,-16.51) 35(0.695,-19.05) 36(3.235,-19.05) 37(0.695,-21.59) 38(3.235,-21.59) 39(0.695,-24.13) 40(3.235,-24.13)
  round 1.95 hole 2 unplated: ""(-3.235,7) ""(-3.235,9.8) ""(-3.235,-9.8) ""(-3.235,-7) ""(-3.235,-4.2) ""(-3.235,-1.4) ""(-3.235,1.4) ""(-3.235,4.2)
  round 4.95 hole 5 unplated: ""(0.665,-29) ""(0.665,29)
  Top Layer lines w0.508: 0.154,-13.97 0.695,-13.97 ; 0.695,-11.688 0.695,-11.43
  silkscreen extent -5.33,-33.27 6.67,33.27, body extent -0.53,-25.8 4.47,25.4, height 8.51
ZIOC-E0800AX [mm]
  rrect50% 1.74x1.5 hole 1: 1(0.695,24.13)
  oval 1.74x1.5 hole 1: 2(3.235,24.13) 3(0.695,21.59) 4(3.235,21.59) 5(0.695,19.05) 6(3.235,19.05) 7(0.695,16.51) 8(3.235,16.51) 9(0.695,13.97) 10(3.235,13.97) 11(0.695,11.43) 12(3.235,11.43) 13(0.695,8.89) 14(3.235,8.89) 15(0.695,6.35) 16(3.235,6.35) 17(0.695,3.81) 18(3.235,3.81) 19(0.695,1.27) 20(3.235,1.27) 21(0.695,-1.27) 22(3.235,-1.27) 23(0.695,-3.81) 24(3.235,-3.81) 25(0.695,-6.35) 26(3.235,-6.35) 27(0.695,-8.89) 28(3.235,-8.89) 29(0.695,-11.43) 30(3.235,-11.43) 31(0.695,-13.97) 32(3.235,-13.97) 33(0.695,-16.51) 34(3.235,-16.51) 35(0.695,-19.05) 36(3.235,-19.05) 37(0.695,-21.59) 38(3.235,-21.59) 39(0.695,-24.13) 40(3.235,-24.13)
  round 1.95 hole 2 unplated: ""(-3.235,7) ""(-3.235,9.8) ""(-3.235,-9.8) ""(-3.235,-7) ""(-3.235,-1.4) ""(-3.235,1.4) ""(-3.235,4.2) ""(-3.218,-4.2)
  round 4.95 hole 5 unplated: ""(0.665,-29) ""(0.665,29)
  silkscreen extent -5.33,-33.27 6.67,33.27, body extent -0.53,-25.8 4.47,25.4, height 8.51
ZIOC-E1600DX [mm]
  rrect50% 1.74x1.5 hole 1: 1(0.695,24.13)
  oval 1.74x1.5 hole 1: 2(3.235,24.13) 3(0.695,21.59) 4(3.235,21.59) 5(0.695,19.05) 6(3.235,19.05) 7(0.695,16.51) 8(3.235,16.51) 9(0.695,13.97) 10(3.235,13.97) 11(0.695,11.43) 12(3.235,11.43) 13(0.695,8.89) 14(3.235,8.89) 15(0.695,6.35) 16(3.235,6.35) 17(0.695,3.81) 18(3.235,3.81) 19(0.695,1.27) 20(3.235,1.27) 21(0.695,-1.27) 22(3.235,-1.27) 23(0.695,-3.81) 24(3.235,-3.81) 25(0.695,-6.35) 26(3.235,-6.35) 27(0.695,-8.89) 28(3.235,-8.89) 29(0.695,-11.43) 30(3.235,-11.43) 31(0.695,-13.97) 32(3.235,-13.97) 33(0.695,-16.51) 34(3.235,-16.51) 35(0.695,-19.05) 36(3.235,-19.05) 37(0.695,-21.59) 38(3.235,-21.59) 39(0.695,-24.13) 40(3.235,-24.13)
  round 1.95 hole 2 unplated: ""(-3.235,7) ""(-3.235,9.8) ""(-3.235,-9.8) ""(-3.235,-7) ""(-3.235,-1.4) ""(-3.235,1.4) ""(-3.235,4.2) ""(-3.218,-4.2)
  round 4.95 hole 5 unplated: ""(0.665,-29) ""(0.665,29)
  Top Layer lines w0.508: 0.154,-13.97 0.164,-13.97 0.695,-13.97 ; 0.695,-11.688 0.695,-11.43
  silkscreen extent -5.33,-33.27 6.67,33.27, body extent -0.53,-25.8 4.47,25.4, height 8.51
ZY_ESD-7 [mm]
  silkscreen extent 0.03,0.03 7.21,6.15
ZY_QC [mm]
  silkscreen extent -6.5,-4.75 6.5,4.75
ZY_UR-3X2 [mm]
  silkscreen extent -1.7,-1.02 2.34,1.7

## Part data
D1 D2: library part 09.04.00227, "SMBJ30A,DO-214AA,BRIGHTKING,"
J1 J2 J3 J4 J5 J6 J7 J8: library part "HEADER 9X2_1"
J9: library part 19.04.00317, "2EDGVC-5.08-03P-14-00AH,180°,THT,DEGSON"
J10: library part 19.04.00316, "2EDGVC-5.08-02P-14-00AH,180°,THT,DEGSON"
U1 U2: library part ZIOC-E1600DX, "数字输入模组"
U3 U4: library part ZIOC-E0016DX, "数字输出模组"
U5: library part ZCPC-80801, "耦合器"
U6 U7: library part ZIOC-E0008AX, "模拟输出模组"
U8 U9: library part ZIOC-E0800AX, "模拟输入模组"

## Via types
v1: diameter 0.559, hole 0.356, Top Layer to Bottom Layer, tented both sides, 99 vias

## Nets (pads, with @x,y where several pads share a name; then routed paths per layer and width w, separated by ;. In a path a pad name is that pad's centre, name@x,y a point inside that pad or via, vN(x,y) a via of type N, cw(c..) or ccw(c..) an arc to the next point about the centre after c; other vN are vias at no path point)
"3.3V ETC": U1.1 U1.2 U2.1 U2.2 U3.1 U3.2 U4.1 U4.2 U5.A2 U5.B1 U5.B2 U6.1 U6.2 U7.1 U7.2 U8.1 U8.2 U9.1 U9.2 | length 435.6
  Top Layer w2.54: U5.A2@-123.03,110.63 U4.2@-62.53,110.63 U9.2@-14.13,110.63
  L3 w2.54: U5.A2@-123.03,110.63 U4.2@-62.53,110.63 U9.2@-14.13,110.63
  L7 w2.54: U5.A2@-123.03,110.63 U4.2@-62.53,110.63 U9.2@-14.13,110.63
  L4 w2.54: U5.A2@-123.03,110.63 U4.2@-62.53,110.63 U9.2@-14.13,110.63
+AI1: J7.15 U8.18 | length 89.1
  Top Layer w1.143: J7.15@-26.862,4.65 -24.206,7.306 -24.206,33.101 -24.905,33.8 -24.905,59.879 -23.609,61.175 -23.609,88.493 -25.425,90.31 U8.18@-26.23,90.31
+AI2: J7.13 U8.20 | length 83.6
  L3 w1.143: J7.13@-26.862,8.15 -24.021,10.991 -24.021,51.766 -23.412,52.375 -23.412,59.51 -22.203,60.718 -22.203,65.82 -22.831,66.448 -22.831,85.08 -25.521,87.77 U8.20@-26.247,87.77
+AI3: J7.11 U8.22 | length 79.6
  L3 w1.143: J7.11@-26.862,11.65 -28.185,11.65 -29.515,12.979 -29.515,36.728 -27.632,38.611 -27.632,51.381 -24.758,54.254 -24.758,60.067 -23.601,61.225 -23.601,65.003 -24.367,65.769 -24.367,84.45 -25.147,85.23 U8.22@-26.247,85.23
+AI4: J7.9 U8.24 | length 72.3
  L6 w1.143: J7.9@-26.862,15.15 -22.511,19.501 -22.511,59.497 -21.38,60.628 -21.38,72.376 -22.904,73.9 -22.904,80.1 -25.495,82.69 U8.24@-26.247,82.69
+AI5: J7.7 U8.26 | length 64.9
  L6 w1.143: J7.7@-26.862,18.65 -24.046,21.467 -24.046,60.118 -22.904,61.259 -22.904,71.295 -24.512,72.903 -24.512,79.086 -25.577,80.15 U8.26@-26.247,80.15
+AI6: J7.5 U8.28 | length 60.8
  L7 w1.143: J7.5@-26.862,22.15 -25.031,22.15 -22.429,24.752 -22.429,59.468 -21.357,60.54 -21.357,72.737 U8.28@-26.23,77.61
+AI7: J7.3 U8.30 | length 52.7
  L7 w1.143: J7.3@-26.862,25.65 -25.595,25.65 -24.372,26.873 -24.372,60.089 -23.429,61.032 -23.429,72.269 U8.30@-26.23,75.07
+AI8: J7.1 U8.32 | length 45.9
  Bottom Layer w1.143: J7.1@-26.862,29.15 -26.862,47.292 -23.456,50.698 -23.456,69.756 U8.32@-26.23,72.53
+AI9: J8.15 U9.18 | length 90
  Top Layer w1.143: U9.18@-14.13,90.31 -13.325,90.31 -11.509,88.493 -11.509,46.736 -15.494,42.751 -15.494,7.432 J8.15@-12.712,4.65
+AI10: J8.13 U9.20 | length 84.4
  L3 w1.143: U9.20@-14.13,87.77 -12.987,87.77 -8.409,83.192 -8.409,12.453 J8.13@-12.712,8.15
+AI11: J8.11 U9.22 | length 77.3
  L3 w1.143: U9.22@-14.13,85.23 -13.012,85.23 -10.263,82.482 -10.263,13.313 -11.926,11.65 J8.11@-12.712,11.65
+AI12: J8.9 U9.24 | length 72.9
  L6 w1.143: U9.24@-14.13,82.69 -13.069,82.69 -10.135,79.756 -10.135,35.941 -8.56,34.366 -8.56,18.034 -11.444,15.15 J8.9@-12.712,15.15
+AI13: J8.7 U9.26 | length 65.4
  L6 w1.143: U9.26@-14.13,80.15 -13.373,80.15 -11.938,78.715 -11.938,34.823 -10.312,33.198 -10.312,19.533 -11.195,18.65 J8.7@-12.712,18.65
+AI14: J8.5 U9.28 | length 59.7
  L7 w1.143: U9.28@-14.13,77.61 -8.255,71.735 -8.255,26.607 J8.5@-12.712,22.15
+AI15: J8.3 U9.30 | length 52.2
  L7 w1.143: U9.30@-14.13,75.07 -10.123,71.063 -10.123,28.239 J8.3@-12.712,25.65
+AI16: J8.1 U9.32 | length 44.5
  L7 w1.143: U9.32@-14.13,72.53 -12.12,70.52 -12.12,29.743 J8.1@-12.712,29.15
-AI1: J7.16 U8.17 | length 91.1
  Top Layer w1.143: J7.16@-32.362,4.65 -36.624,8.912 -36.624,35.382 -35.521,36.485 -35.521,59.447 -34.362,60.605 -34.362,71.85 -30.573,75.639 -30.573,89.239 -29.502,90.31 U8.17@-28.77,90.31
-AI2: J7.14 U8.19 | length 88
  L2 w1.143: -33.53,74.904 -31.337,74.904 -30.569,75.672 -30.569,86.344 -29.143,87.77 U8.19@-28.77,87.77
  L3 w1.143: -33.388,74.93 -32.893,74.435 -32.893,60.225 -34.166,58.952 -34.166,40.941 -36.761,38.345 -36.761,10.498 -34.414,8.15 J7.14@-32.362,8.15
  other v1: -33.479,74.549 -32.869,74.955 -33.479,75.285
-AI3: J7.12 U8.21 | length 79.2
  L3 w1.143: J7.12@-32.362,11.65 -33.291,11.65 -34.874,13.233 -34.874,36.655 -31.598,39.931 -31.598,52.55 -32.82,53.772 -32.82,58.395 -31.491,59.723 -31.491,65.719 -30.635,66.576 -30.635,84.125 -29.53,85.23 U8.21@-28.77,85.23
-AI4: J7.10 U8.23 | length 71.5
  L6 w1.143: J7.10@-32.362,15.15 -34.891,17.679 -34.891,44.357 -32.972,46.276 -32.972,58.801 -31.846,59.927 -31.846,73.896 -30.609,75.133 -30.609,81.485 -29.403,82.69 U8.23@-28.77,82.69
-AI5: J7.8 U8.25 | length 66.2
  L7 w1.143: J7.8@-32.362,18.65 -31.263,18.65 -29.581,20.333 -29.581,48.509 -32.677,51.605 -32.677,58.509 -31.48,59.705 -31.48,73.926 -30.543,74.863 -30.543,78.377 U8.25@-28.77,80.15
-AI6: J7.6 U8.27 | length 60.3
  Bottom Layer w1.143: J7.6@-32.362,22.15 -35.814,25.602 -35.814,31.288 -33.607,33.495 -33.607,72.136 -30.594,75.149 -30.594,76.698 -29.682,77.61 U8.27@-28.77,77.61
-AI7: J7.4 U8.29 | length 53
  Top Layer w1.143: J7.4@-32.362,25.65 -34.721,28.009 -34.721,34.341 -33.973,35.089 -33.973,59.076 -32.952,60.096 -32.952,71.079 -28.961,75.07 U8.29@-28.77,75.07
-AI8: J7.2 U8.31 | length 45.2
  Top Layer w1.143: J7.2@-32.362,29.15 -32.362,58.778 -31.553,59.587 -31.553,70.288 -29.311,72.53 U8.31@-28.77,72.53
-AI9: J8.16 U9.17 | length 91
  Top Layer w1.143: J8.16@-18.212,4.65 -22.474,8.912 -22.474,34.482 -23.421,35.429 -23.421,59.447 -22.262,60.605 -22.262,71.85 -18.473,75.639 -18.473,89.239 -17.402,90.31 U9.17@-16.67,90.31
-AI10: J8.14 U9.19 | length 85.4
  L2 w1.143: -21.43,74.904 -19.237,74.904 -18.469,75.672 -18.469,86.344 -17.043,87.77 U9.19@-16.67,87.77
  L3 w1.143: -21.288,74.93 -20.793,74.435 -20.793,60.225 -22.066,58.952 -22.066,51.079 -21.097,50.11 -21.097,11.034 J8.14@-18.212,8.15
  other v1: -21.379,74.549 -20.769,74.955 -21.379,75.285
-AI11: J8.12 U9.21 | length 78.7
  L3 w1.143: J8.12@-18.212,11.65 -15.9,13.962 -15.9,48.605 -20.72,53.424 -20.72,58.395 -19.391,59.723 -19.391,65.719 -18.535,66.576 -18.535,84.125 -17.43,85.23 U9.21@-16.67,85.23
-AI12: J8.10 U9.23 | length 70.8
  L6 w1.143: J8.10@-18.212,15.15 -20.932,17.869 -20.932,58.741 -19.746,59.927 -19.746,73.896 -18.509,75.133 -18.509,81.485 -17.303,82.69 U9.23@-16.67,82.69
-AI13: J8.8 U9.25 | length 67
  L7 w1.143: J8.8@-18.212,18.65 -17.114,18.65 -15.431,20.333 -15.431,46.297 -20.577,51.443 -20.577,58.509 -19.38,59.705 -19.38,73.926 -18.443,74.863 -18.443,78.377 U9.25@-16.67,80.15
-AI14: J8.6 U9.27 | length 59.4
  Bottom Layer w1.143: J8.6@-18.212,22.15 -21.507,25.445 -21.507,72.136 -18.494,75.149 -18.494,76.698 -17.582,77.61 U9.27@-16.67,77.61
-AI15: J8.4 U9.29 | length 53.2
  Top Layer w1.143: J8.4@-18.212,25.65 -20.571,28.009 -20.571,34.99 -21.873,36.292 -21.873,59.076 -20.852,60.096 -20.852,71.079 -16.861,75.07 U9.29@-16.67,75.07
-AI16: J8.2 U9.31 | length 46.1
  Top Layer w1.143: J8.2@-18.212,29.15 -18.212,35.304 -20.288,37.379 -20.288,58.753 -19.453,59.587 -19.453,70.288 -17.211,72.53 U9.31@-16.67,72.53
AGND1: J5.16 U6.17 | length 92.7
  Top Layer w1.143: J5.16@-60.662,4.65 -64.827,8.815 -64.827,36.089 -59.721,41.195 -59.721,59.447 -58.562,60.605 -58.562,71.85 -54.773,75.639 -54.773,89.239 -53.702,90.31 U6.17@-52.97,90.31
AGND2: J5.14 U6.19 | length 88.3
  L2 w1.143: -57.73,74.904 -55.537,74.904 -54.769,75.672 -54.769,86.344 -53.343,87.77 U6.19@-52.97,87.77
  L3 w1.143: J5.14@-60.662,8.15 -64.901,12.389 -64.901,38.479 -58.366,45.014 -58.366,58.952 -57.093,60.225 -57.093,74.435 -57.588,74.93
  other v1: -57.679,74.549 -57.069,74.955 -57.679,75.285
AGND3: J5.12 U6.21 | length 79.1
  L3 w1.143: J5.12@-60.662,11.65 -62.941,13.929 -62.941,37.648 -57.02,43.57 -57.02,58.395 -55.691,59.723 -55.691,65.719 -54.835,66.576 -54.835,84.125 -53.73,85.23 U6.21@-52.97,85.23
AGND4: J5.10 U6.23 | length 71.1
  L6 w1.143: J5.10@-60.662,15.15 -57.785,18.027 -57.785,30.988 -57.172,31.601 -57.172,58.801 -56.046,59.927 -56.046,73.896 -54.809,75.133 -54.809,81.485 -53.603,82.69 U6.23@-52.97,82.69
AGND5: J5.8 U6.25 | length 64.7
  L7 w1.143: J5.8@-60.662,18.65 -58.003,21.309 -58.003,46.597 -57.189,47.411 -57.189,59.081 -55.697,60.574 -55.697,70.922 -54.864,71.755 -54.864,78.256 U6.25@-52.97,80.15
AGND6: J5.6 U6.27 | length 59.2
  Bottom Layer w1.143: J5.6@-60.662,22.15 -57.807,25.005 -57.807,72.136 -54.794,75.149 -54.794,76.698 -53.882,77.61 U6.27@-52.97,77.61
AGND7: J5.4 U6.29 | length 54.6
  Top Layer w1.143: J5.4@-60.662,25.65 -62.992,27.98 -62.992,35.107 -58.173,39.926 -58.173,59.076 -57.152,60.096 -57.152,71.079 -53.161,75.07 U6.29@-52.97,75.07
AGND8: J5.2 U6.31 | length 46.9
  Top Layer w1.143: J5.2@-60.662,29.15 -60.662,34.77 -56.588,38.844 -56.588,58.753 -55.753,59.587 -55.753,70.288 -53.511,72.53 U6.31@-52.97,72.53
AGND9: J6.16 U7.17 | length 91.6
  Top Layer w1.143: J6.16@-46.512,4.65 -50.39,8.528 -50.39,37.305 -47.621,40.074 -47.621,59.447 -46.462,60.606 -46.462,71.85 -42.673,75.639 -42.673,89.239 -41.602,90.31 U7.17@-40.87,90.31
AGND10: J6.14 U7.19 | length 88.1
  L2 w1.143: -45.63,74.904 -43.437,74.904 -42.669,75.672 -42.669,86.344 -41.243,87.77 U7.19@-40.87,87.77
  L3 w1.143: J6.14@-46.512,8.15 -47.444,8.15 -50.81,11.516 -50.81,38.126 -46.266,42.67 -46.266,58.952 -44.993,60.225 -44.993,74.435 -45.488,74.93
  other v1: -45.579,74.549 -44.969,74.955 -45.579,75.285
AGND11: J6.12 U7.21 | length 78.4
  L3 w1.143: J6.12@-46.512,11.65 -49.022,14.16 -49.022,37.006 -44.92,41.108 -44.92,58.395 -43.591,59.723 -43.591,65.719 -42.735,66.576 -42.735,84.125 -41.63,85.23 U7.21@-40.87,85.23
AGND12: J6.10 U7.23 | length 72.3
  L6 w1.143: J6.10@-46.512,15.15 -49.041,17.679 -49.041,43.87 -45.072,47.839 -45.072,58.801 -43.946,59.927 -43.946,73.896 -42.709,75.133 -42.709,81.485 -41.503,82.69 U7.23@-40.87,82.69
AGND13: J6.8 U7.25 | length 64.6
  L7 w1.143: J6.8@-46.512,18.65 -43.815,21.347 -43.815,32.995 -44.777,33.956 -44.777,58.509 -43.58,59.705 -43.58,73.926 -42.643,74.863 -42.643,78.377 U7.25@-40.87,80.15
AGND14: J6.6 U7.27 | length 61
  Bottom Layer w1.143: J6.6@-46.512,22.15 -49.784,25.422 -49.784,44.743 -45.707,48.82 -45.707,72.136 -42.694,75.149 -42.694,76.698 -41.782,77.61 U7.27@-40.87,77.61
AGND15: J6.4 U7.29 | length 54.1
  Top Layer w1.143: J6.4@-46.512,25.65 -47.184,25.65 -48.677,27.142 -48.677,36.415 -46.073,39.019 -46.073,59.076 -45.052,60.096 -45.052,71.079 -41.061,75.07 U7.29@-40.87,75.07
AGND16: J6.2 U7.31 | length 46
  Top Layer w1.143: J6.2@-46.512,29.15 -46.512,36.018 -44.488,38.042 -44.488,58.753 -43.653,59.587 -43.653,70.288 -41.411,72.53 U7.31@-40.87,72.53
AO1: J5.15 U6.18 | length 92.7
  Top Layer w1.143: J5.15@-55.162,4.65 -57.912,7.4 -57.912,32.512 -49.126,41.298 -49.126,59.858 -47.809,61.175 -47.809,88.813 -49.305,90.31 U6.18@-50.43,90.31
AO2: J5.13 U6.20 | length 85.3
  L3 w1.143: J5.13@-55.162,8.15 -52.619,10.693 -52.619,39.543 -47.612,44.55 -47.612,59.51 -46.403,60.718 -46.403,65.82 -47.031,66.448 -47.031,85.08 -49.721,87.77 U6.20@-50.447,87.77
AO3: J5.11 U6.22 | length 80.6
  L3 w1.143: J5.11@-55.162,11.65 -57.861,14.349 -57.861,37.59 -48.958,46.493 -48.958,60.067 -47.801,61.225 -47.801,65.003 -48.567,65.769 -48.567,84.45 -49.347,85.23 U6.22@-50.447,85.23
AO4: J5.9 U6.24 | length 74
  L6 w1.143: J5.9@-55.162,15.15 -50.862,19.45 -50.862,45.385 -46.717,49.53 -46.717,59.491 -45.58,60.628 -45.58,72.376 -47.104,73.9 -47.104,80.1 -49.695,82.69 U6.24@-50.447,82.69
AO5: J5.7 U6.26 | length 66.6
  L6 w1.143: J5.7@-55.162,18.65 -52.648,21.164 -52.648,46.459 -48.247,50.86 -48.247,60.116 -47.104,61.259 -47.104,71.295 -48.712,72.903 -48.712,79.086 -49.777,80.15 U6.26@-50.447,80.15
AO6: J5.5 U6.28 | length 63
  L7 w1.143: J5.5@-55.162,22.15 -52.847,22.15 -49.642,25.355 -49.642,45.622 -46.689,48.575 -46.689,59.058 -45.381,60.365 -45.381,72.561 U6.28@-50.43,77.61
AO7: J5.3 U6.30 | length 55
  L7 w1.143: J5.3@-55.162,25.65 -53.397,25.65 -51.755,27.292 -51.755,47.014 -48.783,49.985 -48.783,59.395 -47.286,60.892 -47.286,71.926 U6.30@-50.43,75.07
AO8: J5.1 U6.32 | length 47.6
  Bottom Layer w1.143: J5.1@-55.162,29.15 -55.162,44.169 -47.656,51.675 -47.656,69.756 U6.32@-50.43,72.53
AO9: J6.15 U7.18 | length 89.4
  Top Layer w1.143: J6.15@-41.012,4.65 -38.499,7.163 -38.499,36.634 -37.005,38.128 -37.005,59.879 -35.709,61.175 -35.709,88.437 -37.582,90.31 U7.18@-38.33,90.31
AO10: J6.13 U7.20 | length 84.5
  L3 w1.143: J6.13@-41.012,8.15 -38.557,10.605 -38.557,39.642 -35.512,42.687 -35.512,59.51 -34.303,60.718 -34.303,65.82 -34.931,66.448 -34.931,85.08 -37.621,87.77 U7.20@-38.347,87.77
AO11: J6.11 U7.22 | length 80.3
  L3 w1.143: J6.11@-41.012,11.65 -41.673,11.65 -43.933,13.91 -43.933,37.358 -36.858,44.432 -36.858,60.067 -35.701,61.225 -35.701,65.003 -36.467,65.769 -36.467,84.45 -37.247,85.23 U7.22@-38.347,85.23
AO12: J6.9 U7.24 | length 73.1
  L6 w1.143: J6.9@-41.012,15.15 -36.712,19.45 -36.712,45.584 -34.617,47.679 -34.617,59.491 -33.48,60.628 -33.48,72.376 -35.004,73.9 -35.004,80.1 -37.595,82.69 U7.24@-38.347,82.69
AO13: J6.7 U7.26 | length 65.8
  L6 w1.143: J6.7@-41.012,18.65 -38.498,21.164 -38.498,46.798 -36.147,49.149 -36.147,60.116 -35.004,61.259 -35.004,71.295 -36.612,72.903 -36.612,79.086 -37.677,80.15 U7.26@-38.347,80.15
AO14: J6.5 U7.28 | length 61.7
  L7 w1.143: J6.5@-41.012,22.15 -39.181,22.15 -35.695,25.636 -35.695,48.817 -34.798,49.713 -34.798,59.177 -33.458,60.517 -33.458,72.738 U7.28@-38.33,77.61
AO15: J6.3 U7.30 | length 53
  L7 w1.143: J6.3@-41.012,25.65 -38.456,28.206 -38.456,49.578 -36.853,51.181 -36.853,59.579 -35.333,61.099 -35.333,72.073 U7.30@-38.33,75.07
AO16: J6.1 U7.32 | length 46.8
  Bottom Layer w1.143: J6.1@-41.012,29.15 -41.012,46.228 -35.556,51.684 -35.556,69.756 U7.32@-38.33,72.53
DI1: J1.15 U1.18 | length 93.7
  Top Layer w1.143: J1.15@-111.761,4.65 -109.248,7.163 -109.248,32.131 -97.505,43.874 -97.505,59.879 -96.209,61.175 -96.209,88.565 -97.954,90.31 U1.18@-98.847,90.31
DI2: J1.13 U1.20 | length 88.7
  L3 w1.143: J1.13@-111.761,8.15 -107.543,12.368 -107.543,38.781 -96.012,50.312 -96.012,59.51 -94.803,60.718 -94.803,73.358 -95.531,74.085 -95.531,85.18 -98.121,87.77 U1.20@-98.847,87.77
DI3: J1.11 U1.22 | length 81.8
  L3 w1.143: J1.11@-111.761,11.65 -109.288,14.123 -109.288,40.952 -97.358,52.882 -97.358,60.067 -96.201,61.225 -96.201,72.782 -96.895,73.476 -96.895,84.378 -97.747,85.23 U1.22@-98.847,85.23
DI4: J1.9 U1.24 | length 77.4
  L6 w1.143: J1.9@-111.761,15.15 -106.241,20.67 -106.241,40.022 -95.117,51.146 -95.117,59.491 -93.98,60.628 -93.98,72.376 -95.504,73.9 -95.504,80.1 -98.095,82.69 U1.24@-98.847,82.69
DI5: J1.7 U1.26 | length 70
  L6 w1.143: J1.7@-111.761,18.65 -108.116,22.295 -108.116,42.54 -96.647,54.009 -96.647,60.116 -95.504,61.259 -95.504,71.295 -97.112,72.903 -97.112,79.086 -98.177,80.15 U1.26@-98.847,80.15
DI6: J1.5 U1.28 | length 66.1
  L7 w1.143: J1.5@-111.761,22.15 -109.93,22.15 -106.089,25.991 -106.089,42.102 -95.232,52.96 -95.232,58.894 -93.802,60.324 -93.802,72.582 U1.28@-98.83,77.61
DI7: J1.3 U1.30 | length 58
  L7 w1.143: J1.3@-111.761,25.65 -110.494,25.65 -108.839,27.305 -108.839,43.746 -97.294,55.291 -97.294,59.284 -95.798,60.78 -95.798,72.038 U1.30@-98.83,75.07
DI8: J1.1 U1.32 | length 51.2
  Bottom Layer w1.143: J1.1@-111.761,29.15 -111.761,39.47 -95.877,55.354 -95.877,69.56 U1.32@-98.847,72.53
DI9: J1.16 U1.17 | length 96.8
  Top Layer w1.143: J1.16@-117.261,4.65 -118.264,4.65 -119.958,6.344 -119.958,24.925 -121.505,26.471 -121.505,31.745 -109.877,43.373 -109.877,59.454 -107.319,62.012 -107.319,71.599 -103.19,75.727 -103.19,89.239 -102.119,90.31 U1.17@-101.387,90.31
DI10: J1.14 U1.19 | length 90.6
  L2 w1.143: -106.147,74.905 -103.954,74.905 -103.186,75.673 -103.186,86.344 -101.76,87.77 U1.19@-101.387,87.77
  L3 w1.143: J1.14@-117.261,8.15 -119.761,10.65 -119.761,37.761 -107.697,49.825 -107.697,74.04 -106.807,74.93 v1@-105.715,74.93
  other v1: -106.096,74.549 -105.486,74.955 -106.096,75.286
DI11: J1.12 U1.21 | length 80.4
  L3 w1.143: J1.12@-117.261,11.65 -114.935,13.976 -114.935,39.126 -105.788,48.273 -105.788,72.639 -103.302,75.125 -103.302,83.782 -101.853,85.23 U1.21@-101.387,85.23
DI12: J1.10 U1.23 | length 75.2
  L6 w1.143: J1.10@-117.261,15.15 -116.092,15.15 -114.427,16.815 -114.427,41.496 -105.901,50.022 -105.901,72.458 -103.226,75.133 -103.226,81.485 -102.02,82.69 U1.23@-101.387,82.69
DI13: J1.8 U1.25 | length 68.1
  L7 w1.143: J1.8@-117.261,18.65 -114.681,21.23 -114.681,43.07 -105.518,52.232 -105.518,70.173 -103.327,72.365 -103.327,78.21 U1.25@-101.387,80.15
DI14: J1.6 U1.27 | length 62.6
  Bottom Layer w1.143: J1.6@-117.261,22.15 -114.706,24.705 -114.706,43.061 -106.145,51.622 -106.145,72.518 -103.099,75.565 -103.099,76.81 -102.298,77.61 U1.27@-101.387,77.61
DI15: J1.4 U1.29 | length 58
  Top Layer w1.143: J1.4@-117.293,25.65 -119.478,27.835 -119.478,31.328 -108.063,42.743 -108.063,59.175 -105.873,61.365 -105.873,70.928 -101.73,75.07 U1.29@-101.387,75.07
DI16: J1.2 U1.31 | length 51
  Top Layer w1.143: J1.2@-117.261,29.15 -117.261,31.1 -106.21,42.151 -106.21,58.954 -104.288,60.876 -104.288,70.485 -102.243,72.53 U1.31@-101.387,72.53 U1.31@-101.928,72.53
DI17: J2.15 U2.18 | length 92.9
  Top Layer w1.143: J2.15@-97.612,4.65 -95.098,7.163 -95.098,32.842 -85.405,42.536 -85.405,59.879 -84.109,61.175 -84.109,88.663 -85.755,90.31 U2.18@-86.73,90.31
DI18: J2.13 U2.20 | length 87.9
  L3 w1.143: J2.13@-97.612,8.15 -95.25,10.511 -95.25,39.679 -83.912,51.017 -83.912,59.51 -82.703,60.718 -82.703,65.82 -83.331,66.448 -83.331,85.08 -86.021,87.77 U2.20@-86.747,87.77
DI19: J2.11 U2.22 | length 82.6
  L3 w1.143: J2.11@-97.612,11.65 -99.65,13.688 -99.65,38.177 -85.258,52.568 -85.258,60.067 -84.101,61.225 -84.101,65.003 -84.867,65.769 -84.867,84.45 -85.647,85.23 U2.22@-86.747,85.23
DI20: J2.9 U2.24 | length 76.5
  L6 w1.143: J2.9@-97.612,15.15 -91.654,21.108 -91.654,41.763 -83.017,50.4 -83.017,59.491 -81.88,60.628 -81.88,72.376 -83.404,73.9 -83.404,80.1 -85.995,82.69 U2.24@-86.747,82.69
DI21: J2.7 U2.26 | length 69.2
  L6 w1.143: J2.7@-97.612,18.65 -94.224,22.038 -94.224,42.155 -84.547,51.832 -84.547,60.116 -83.404,61.259 -83.404,71.295 -85.012,72.903 -85.012,79.086 -86.077,80.15 U2.26@-86.747,80.15
DI22: J2.5 U2.28 | length 65
  L7 w1.143: J2.5@-97.612,22.15 -95.78,22.15 -92.403,25.527 -92.403,42.261 -83.128,51.536 -83.128,58.801 -81.945,59.985 -81.945,72.825 U2.28@-86.73,77.61
DI23: J2.3 U2.30 | length 57
  L7 w1.143: J2.3@-97.612,25.65 -96.344,25.65 -94.689,27.305 -94.689,43.839 -85.118,53.41 -85.118,59.392 -83.913,60.598 -83.913,72.253 U2.30@-86.73,75.07
DI24: J2.1 U2.32 | length 50.2
  Bottom Layer w1.143: J2.1@-97.612,29.15 -97.612,42.278 -83.956,55.933 -83.956,69.756 U2.32@-86.73,72.53
DI25: J2.16 U2.17 | length 95.4
  Top Layer w1.143: J2.16@-103.112,4.65 -107.373,8.912 -107.373,31.057 -96.021,42.409 -96.021,59.447 -94.862,60.605 -94.862,71.85 -91.073,75.639 -91.073,89.239 -90.002,90.31 U2.17@-89.27,90.31
DI26: J2.14 U2.19 | length 89.5
  L2 w1.143: -94.03,74.904 -91.837,74.904 -91.069,75.672 -91.069,86.344 -89.643,87.77 U2.19@-89.27,87.77
  L3 w1.143: J2.14@-103.112,8.15 -105.732,10.771 -105.732,37.771 -94.666,48.837 -94.666,58.952 -93.393,60.225 -93.393,74.572 -93.802,74.981
  other v1: -93.979,74.549 -93.369,74.955 -93.979,75.285
DI27: J2.12 U2.21 | length 79.8
  L3 w1.143: J2.12@-103.112,11.65 -101.095,13.667 -101.095,39.718 -93.32,47.493 -93.32,58.395 -91.991,59.723 -91.991,72.829 -91.135,73.685 -91.135,84.125 -90.03,85.23 U2.21@-89.27,85.23
DI28: J2.10 U2.23 | length 73.6
  L6 w1.143: J2.10@-103.112,15.15 -100.711,17.55 -100.711,41.109 -93.472,48.348 -93.472,58.801 -92.346,59.927 -92.346,73.896 -91.109,75.133 -91.109,81.485 -89.903,82.69 U2.23@-89.27,82.69
DI29: J2.8 U2.25 | length 67.9
  L7 w1.143: J2.8@-103.112,18.65 -102.013,18.65 -100.33,20.333 -100.33,42.738 -93.177,49.892 -93.177,58.509 -91.98,59.705 -91.98,73.926 -91.043,74.863 -91.043,78.377 U2.25@-89.27,80.15
DI30: J2.6 U2.27 | length 61.7
  Bottom Layer w1.143: J2.6@-103.112,22.15 -100.609,24.652 -100.609,46.231 -93.769,53.072 -93.769,72.474 -91.094,75.149 -91.094,76.698 -90.182,77.61 U2.27@-89.27,77.61
DI31: J2.4 U2.29 | length 57.2
  Top Layer w1.143: J2.4@-103.112,25.65 -105.47,28.009 -105.47,30.42 -94.473,41.417 -94.473,59.076 -93.452,60.096 -93.452,71.079 -89.461,75.07 U2.29@-89.27,75.07
DI32: J2.2 U2.31 | length 49.4
  Top Layer w1.143: J2.2@-103.112,29.15 -103.112,30.238 -92.888,40.462 -92.888,58.753 -92.053,59.587 -92.053,70.288 -89.811,72.53 -89.801,72.53 U2.31@-89.27,72.53
DO1: J3.15 U3.18 | length 92.1
  Top Layer w1.143: J3.15@-83.462,4.65 -80.949,7.163 -80.949,35.154 -73.305,42.798 -73.305,59.879 -72.009,61.175 -72.009,88.7 -73.619,90.31 U3.18@-74.63,90.31
DO2: J3.13 U3.20 | length 87
  L3 w1.143: J3.13@-83.462,8.15 -81.026,10.586 -81.026,41.503 -71.812,50.717 -71.812,59.51 -70.603,60.718 -70.603,65.82 -71.231,66.448 -71.231,85.08 -73.921,87.77 U3.20@-74.647,87.77
DO3: J3.11 U3.22 | length 83
  L3 w1.143: J3.11@-83.462,11.65 -84.421,11.65 -86.36,13.589 -86.36,39.152 -73.158,52.354 -73.158,60.067 -72.001,61.225 -72.001,65.003 -72.767,65.769 -72.767,84.45 -73.547,85.23 U3.22@-74.647,85.23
